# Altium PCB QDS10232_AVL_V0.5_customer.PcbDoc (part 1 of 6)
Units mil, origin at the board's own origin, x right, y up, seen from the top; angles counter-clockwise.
Board outline 3500 x 3799 mil, 6 copper layers (Top Layer, GND, INT1, PWR1, PWR2, Bottom Layer), stack 78.834 mil thick; 254 components, 204 nets, 7039 pads, 595 vias.
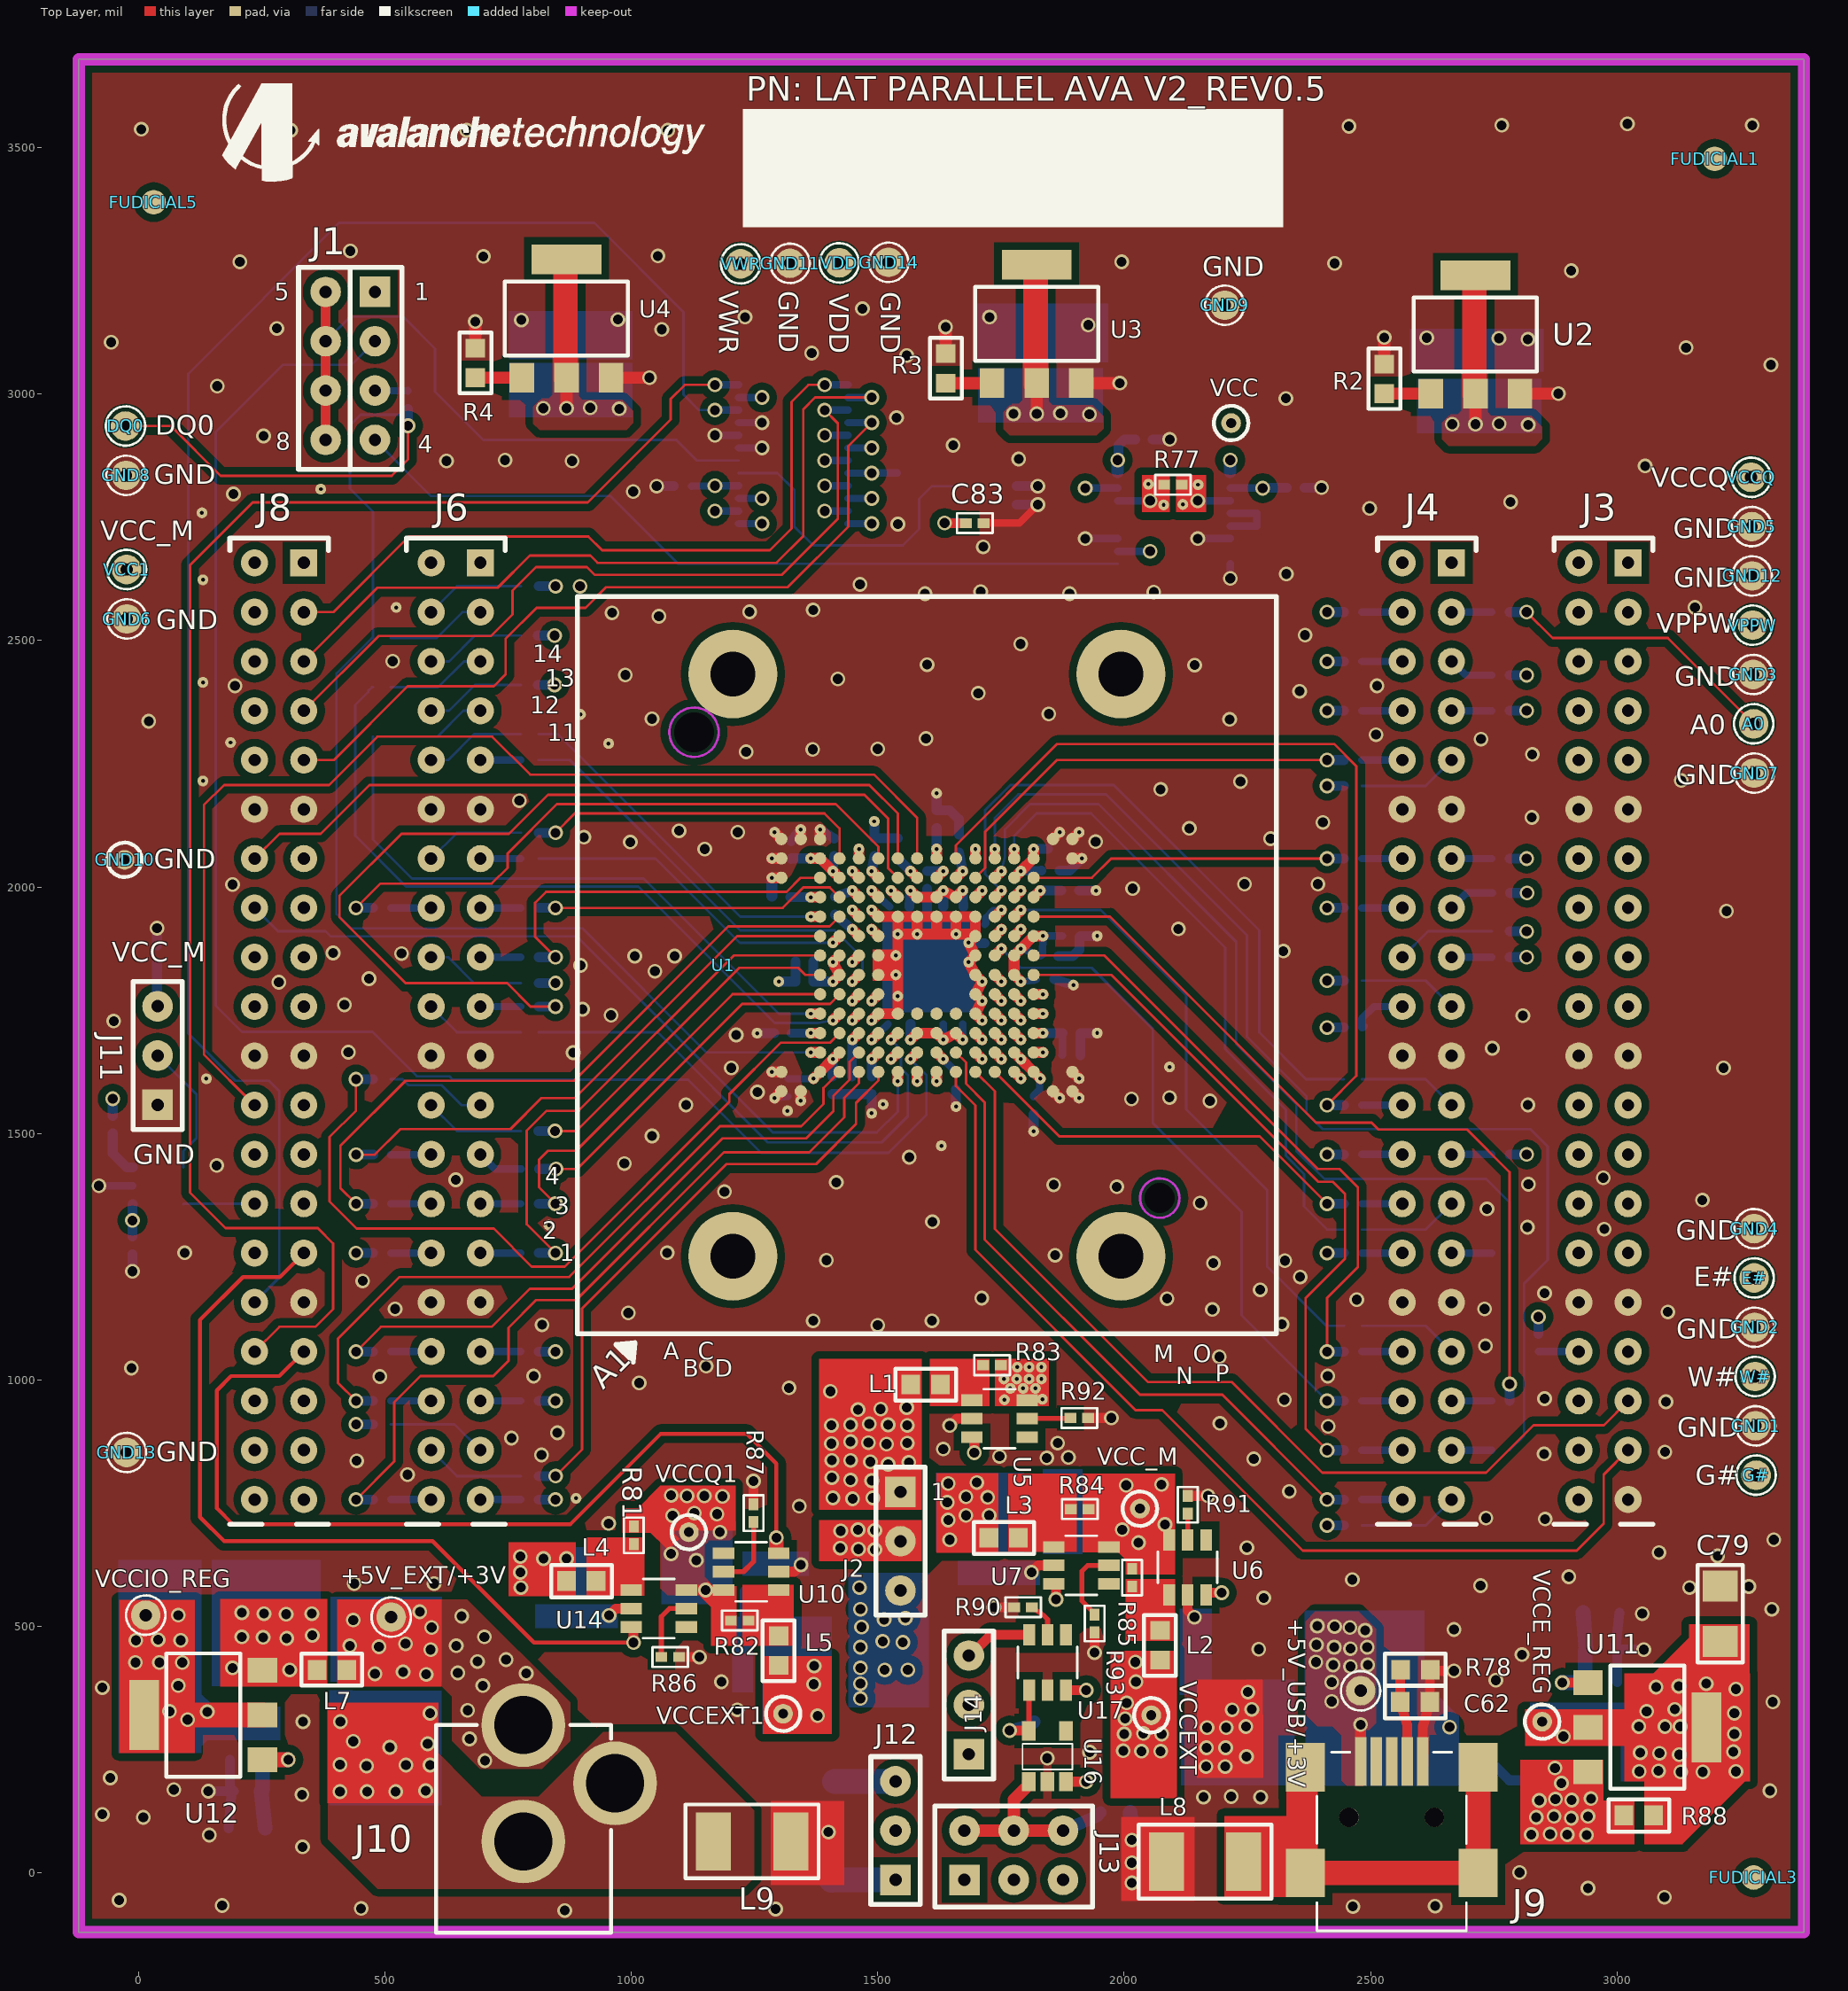
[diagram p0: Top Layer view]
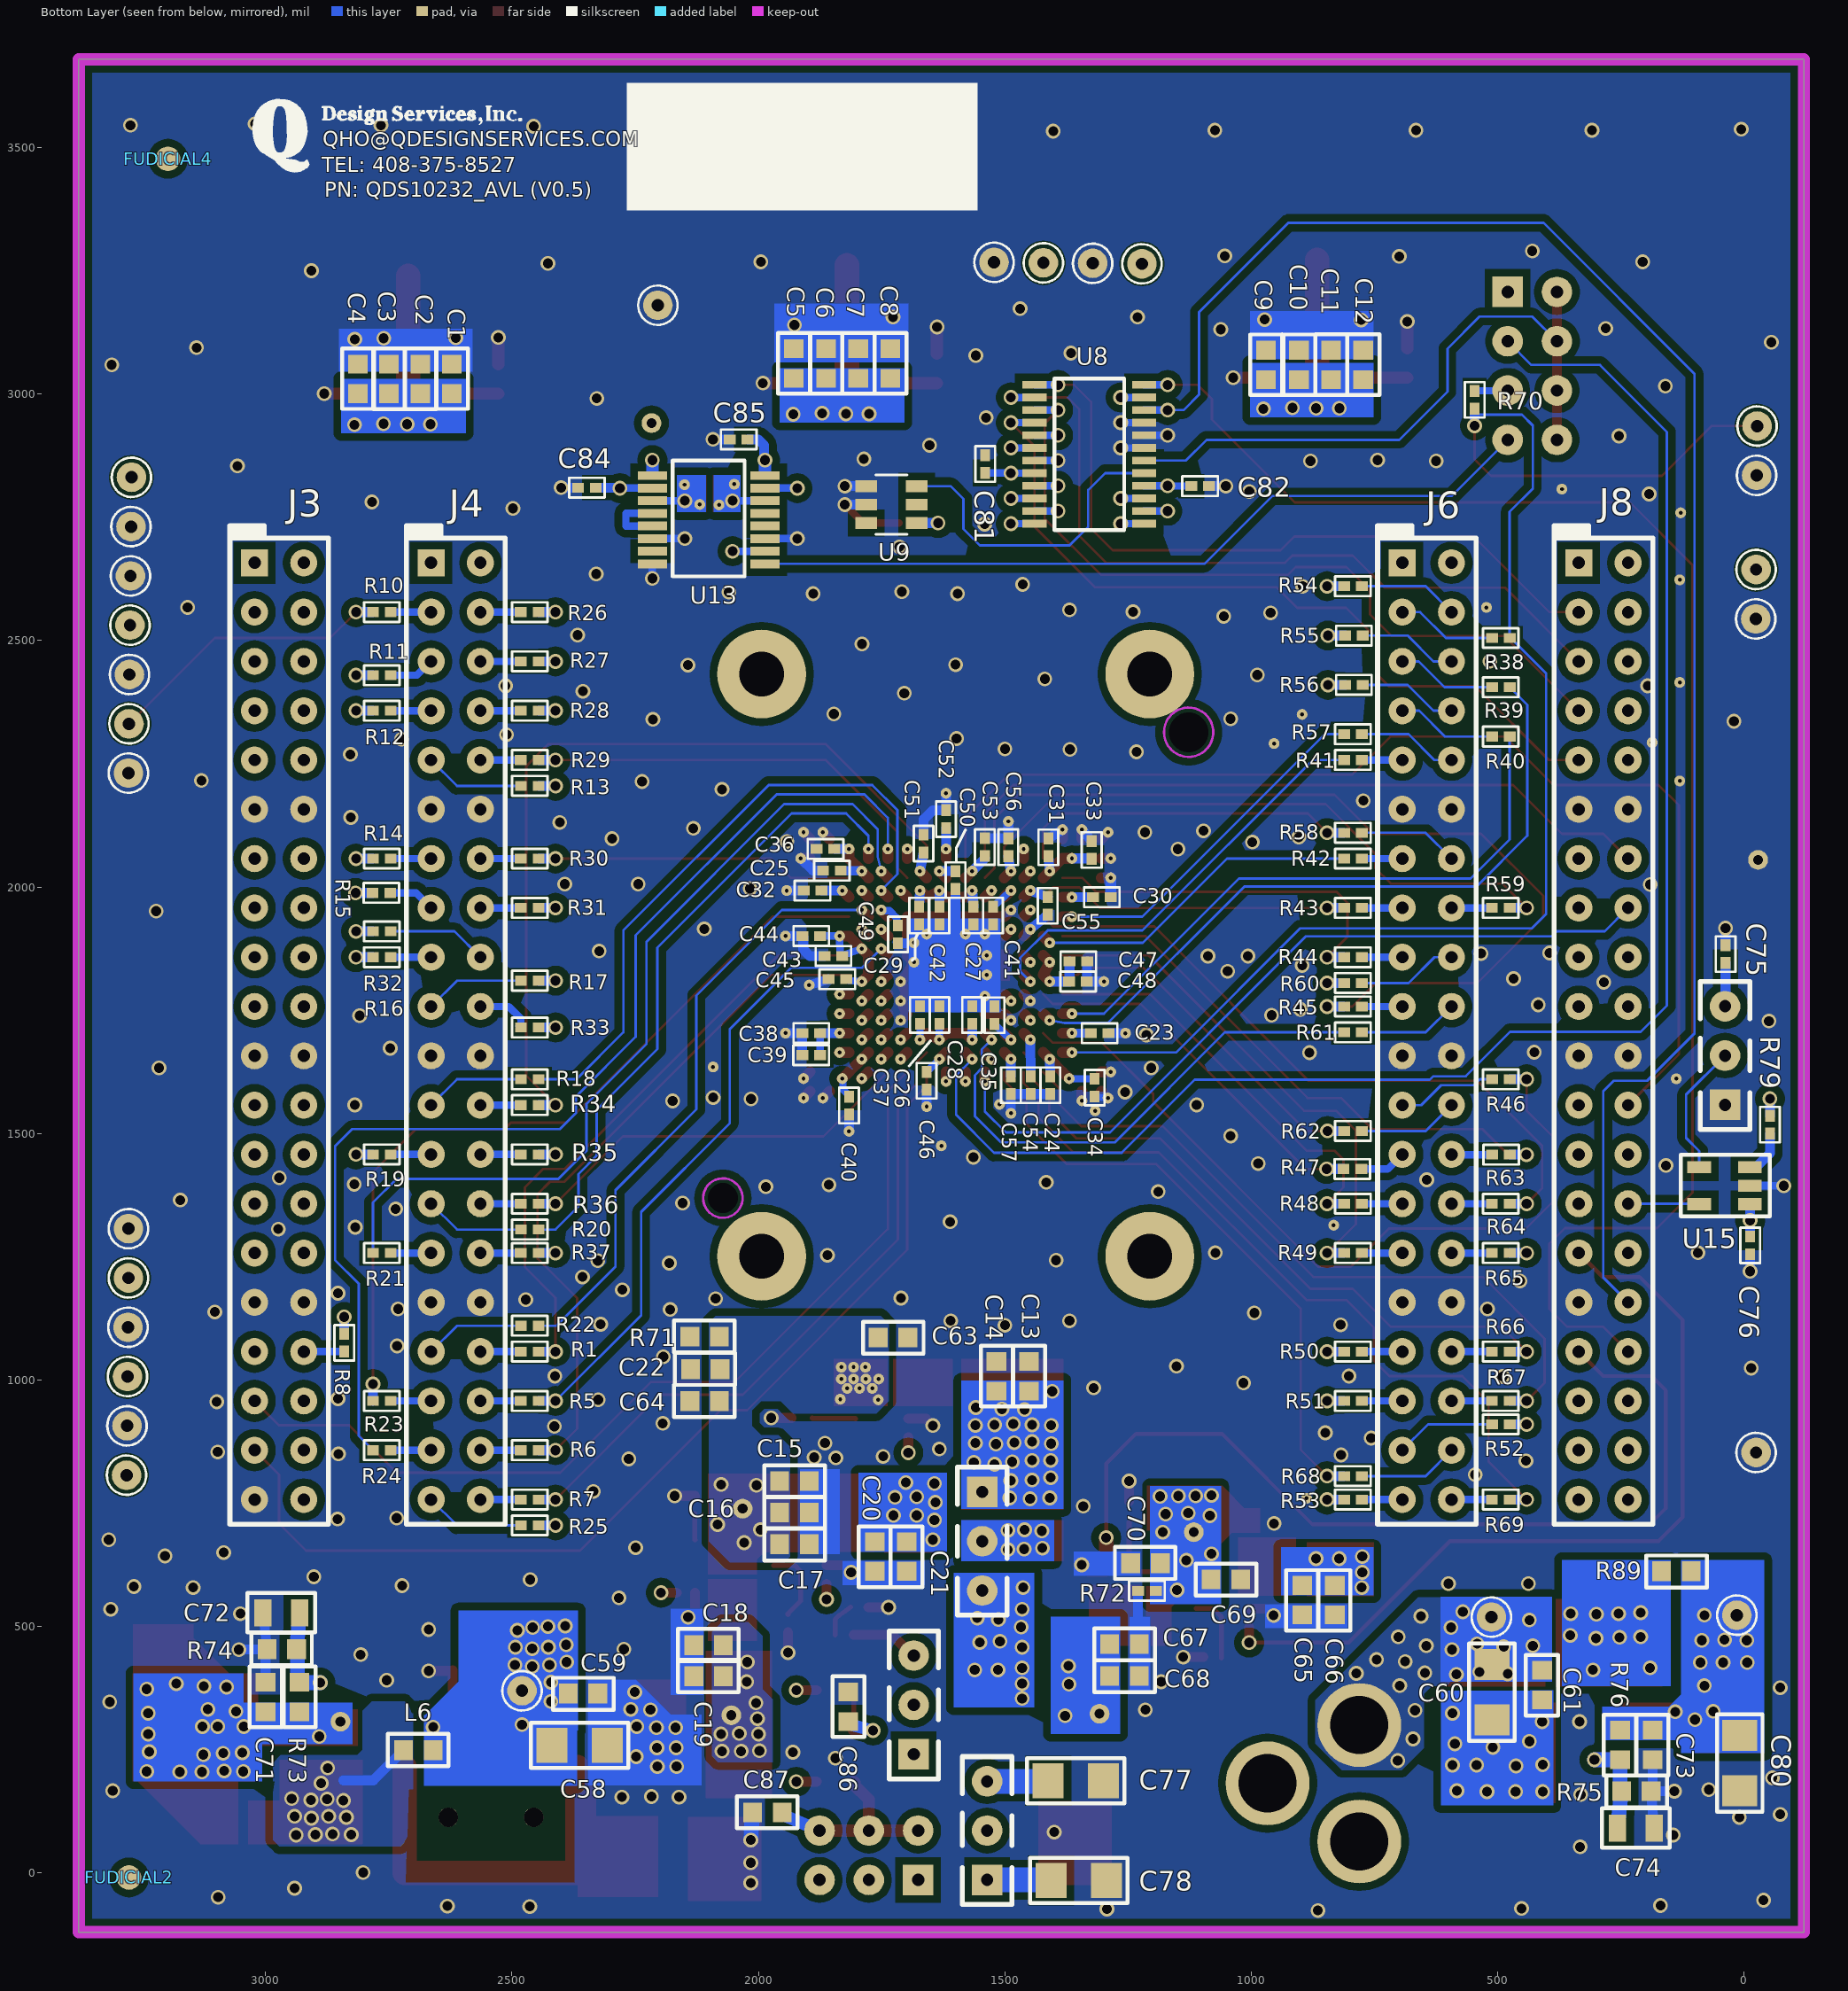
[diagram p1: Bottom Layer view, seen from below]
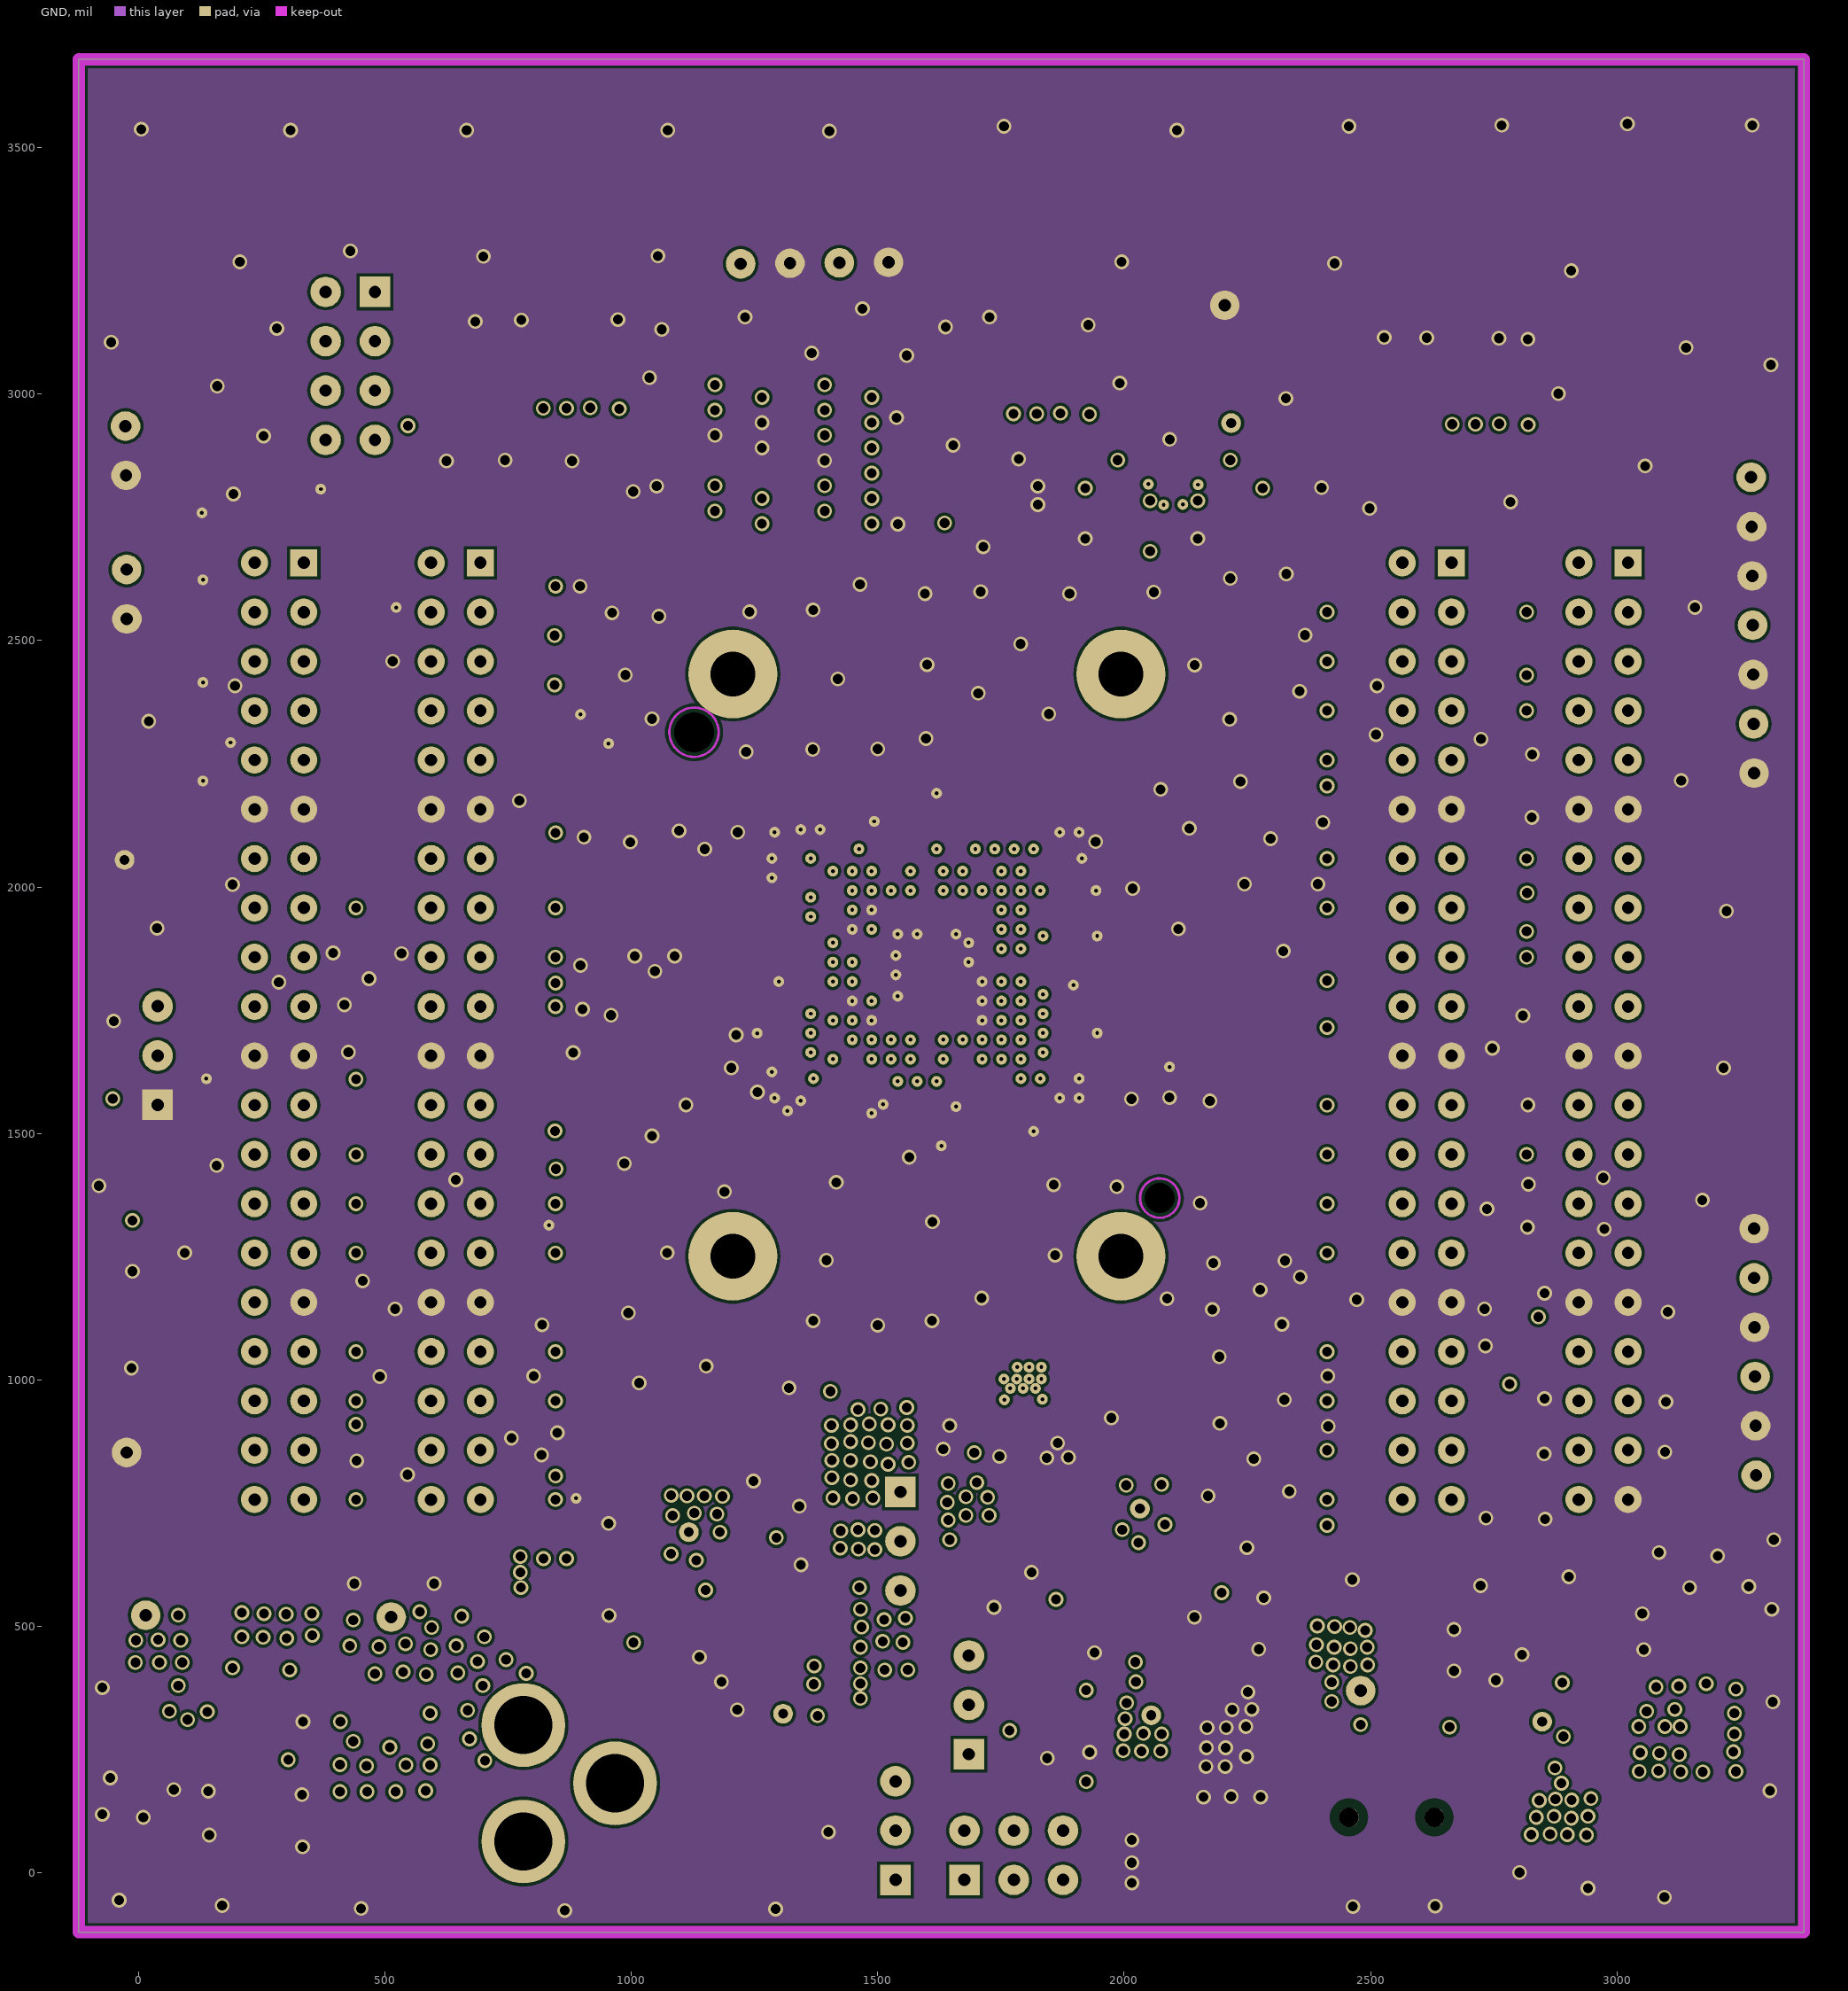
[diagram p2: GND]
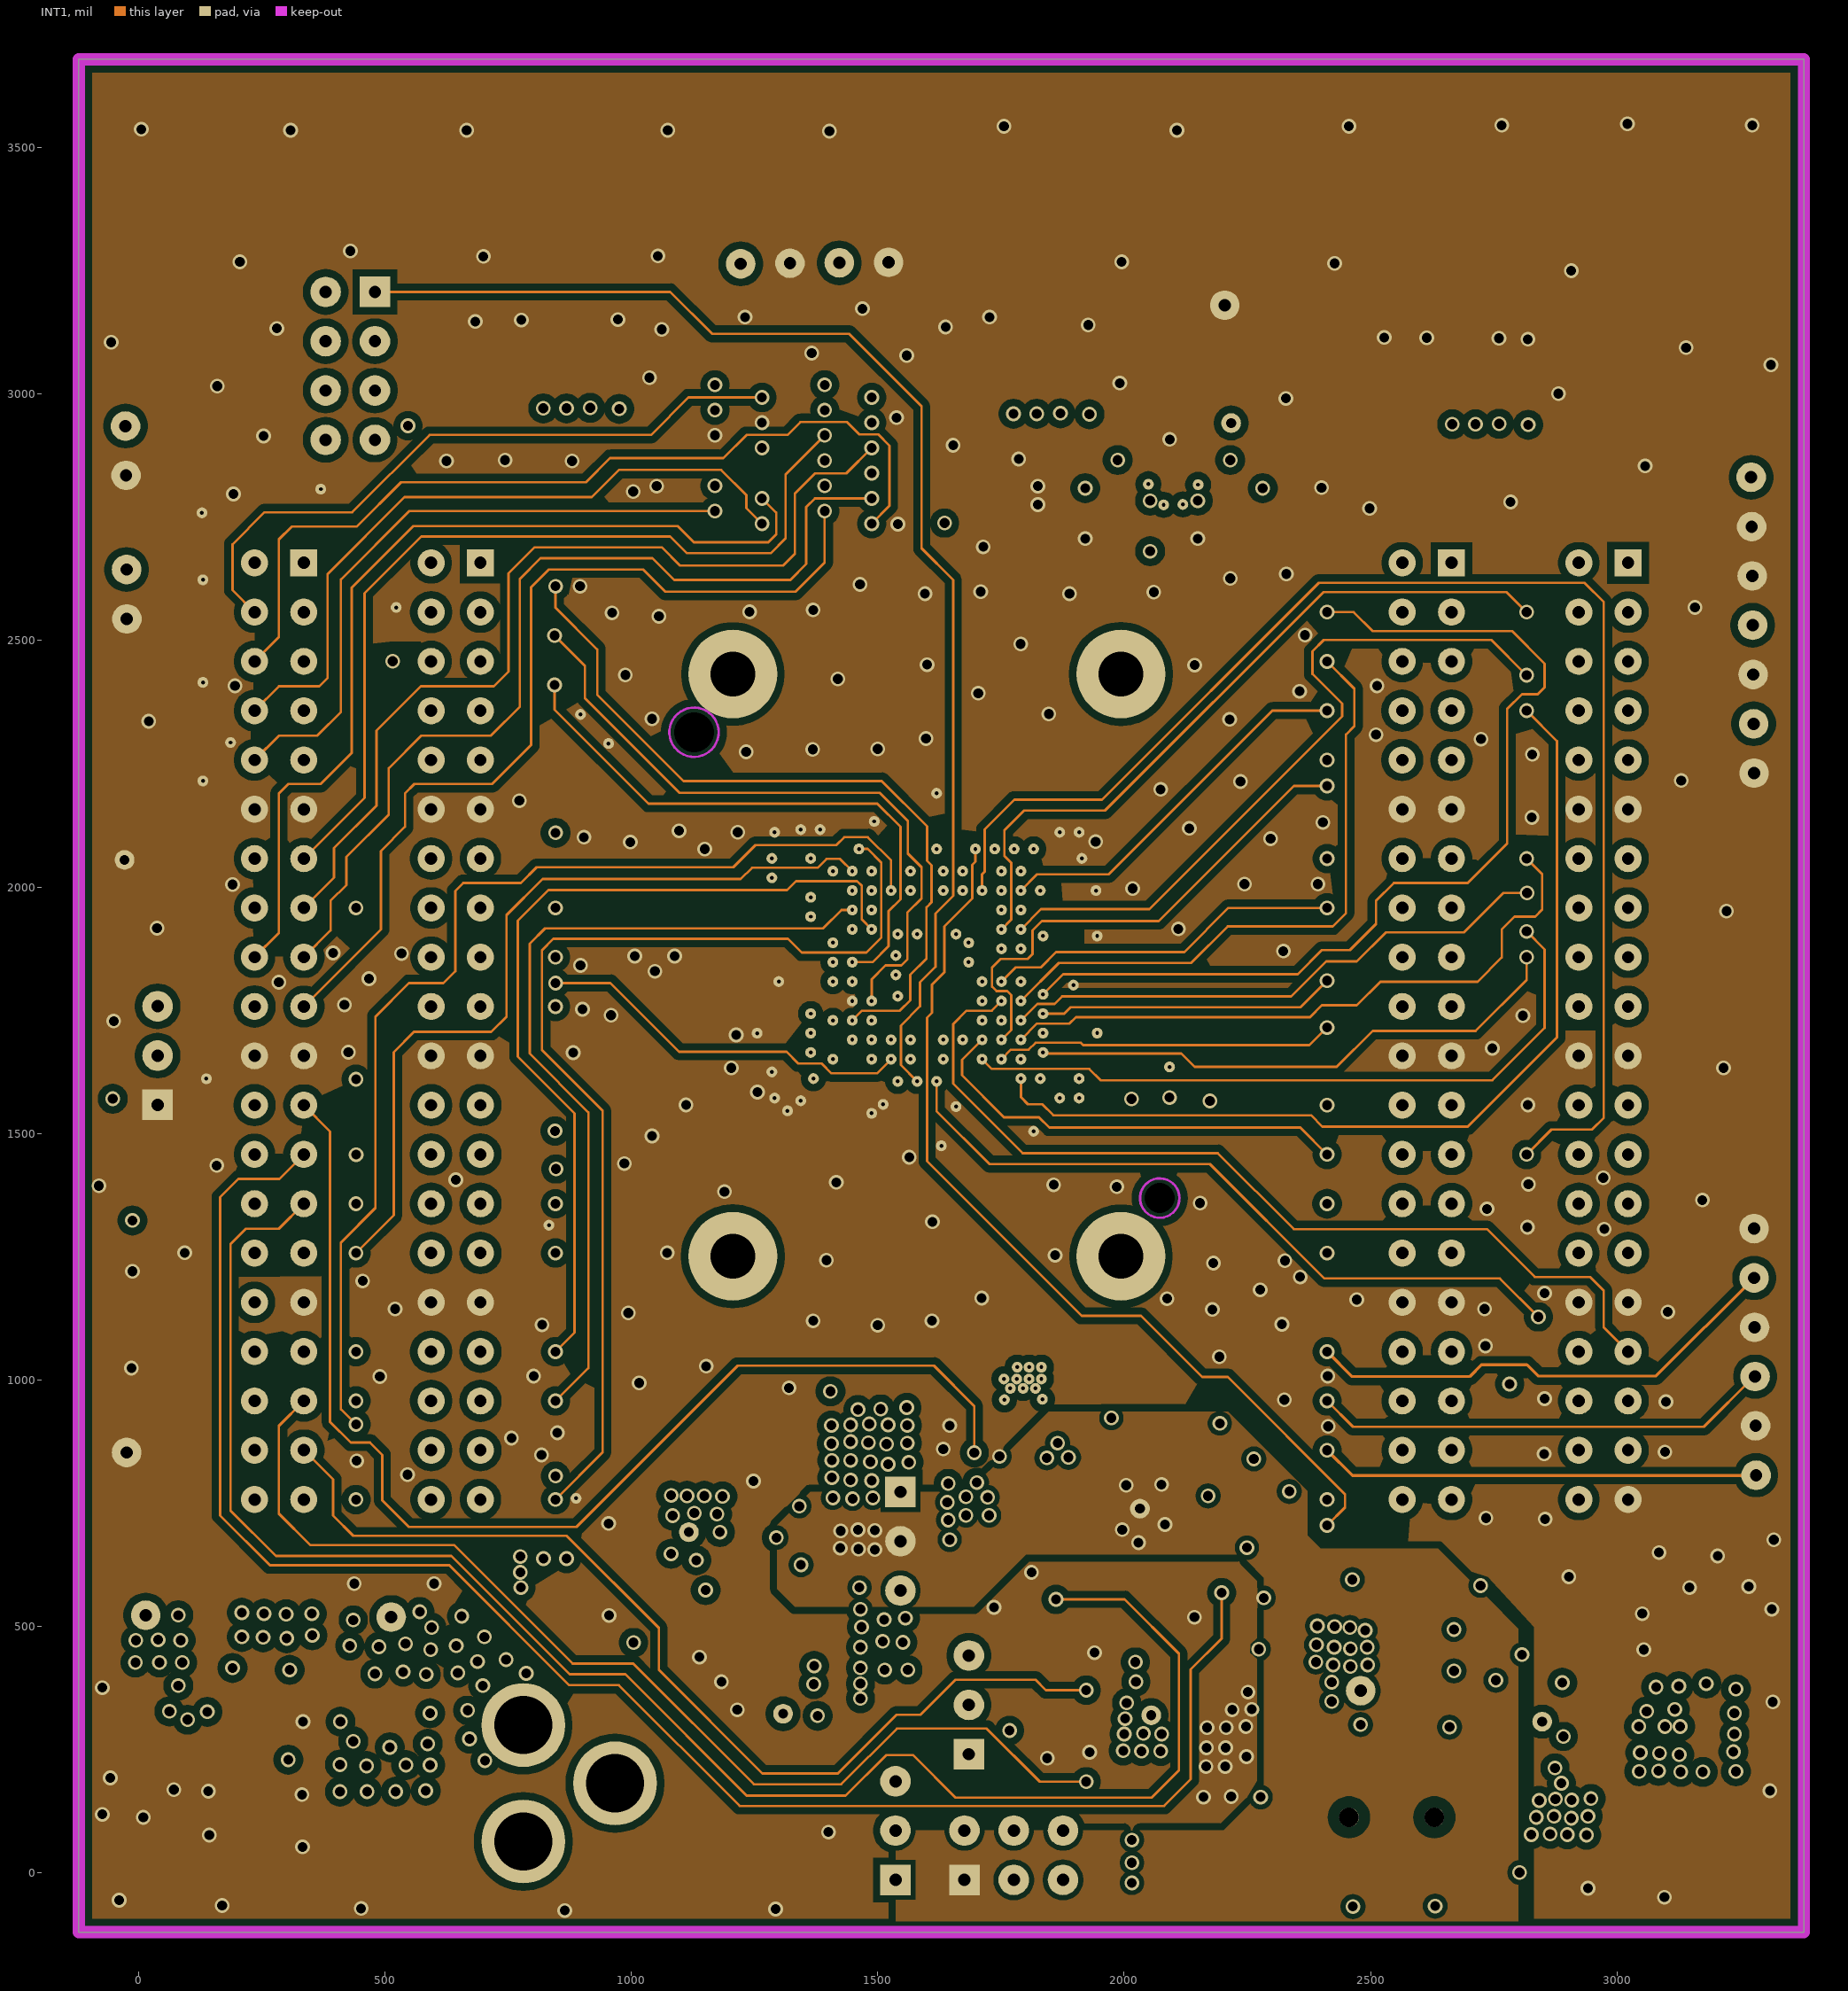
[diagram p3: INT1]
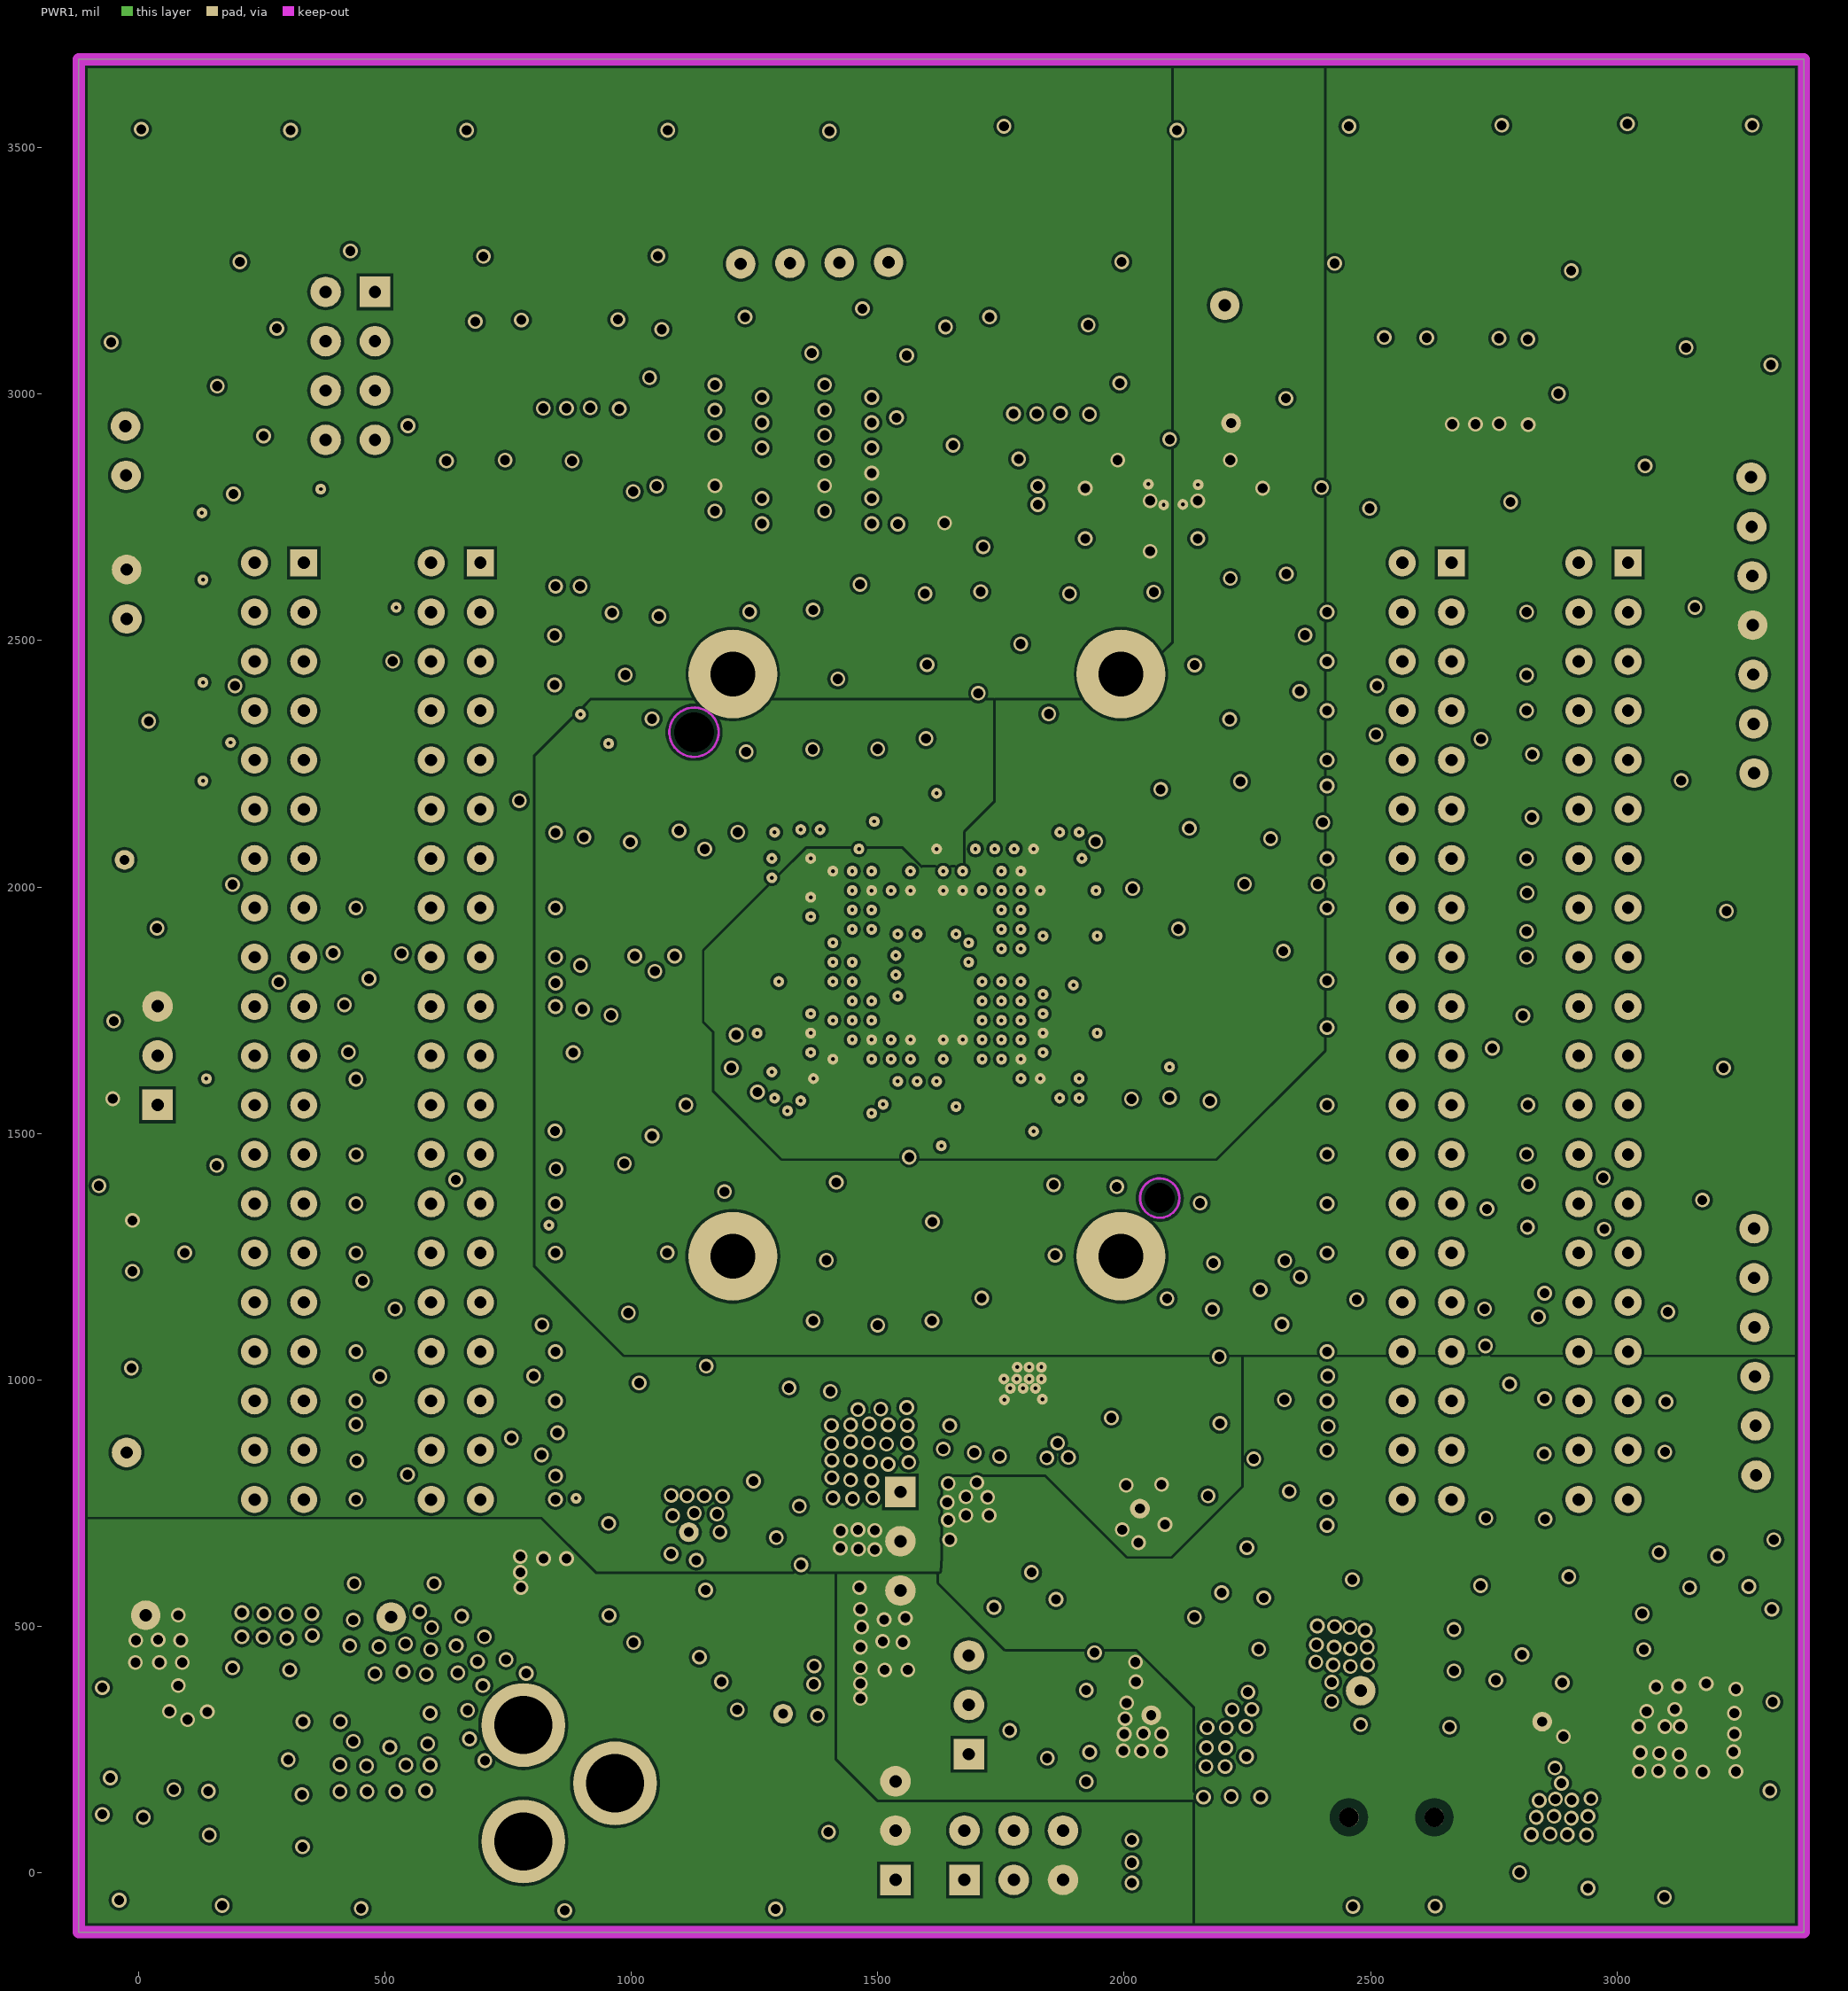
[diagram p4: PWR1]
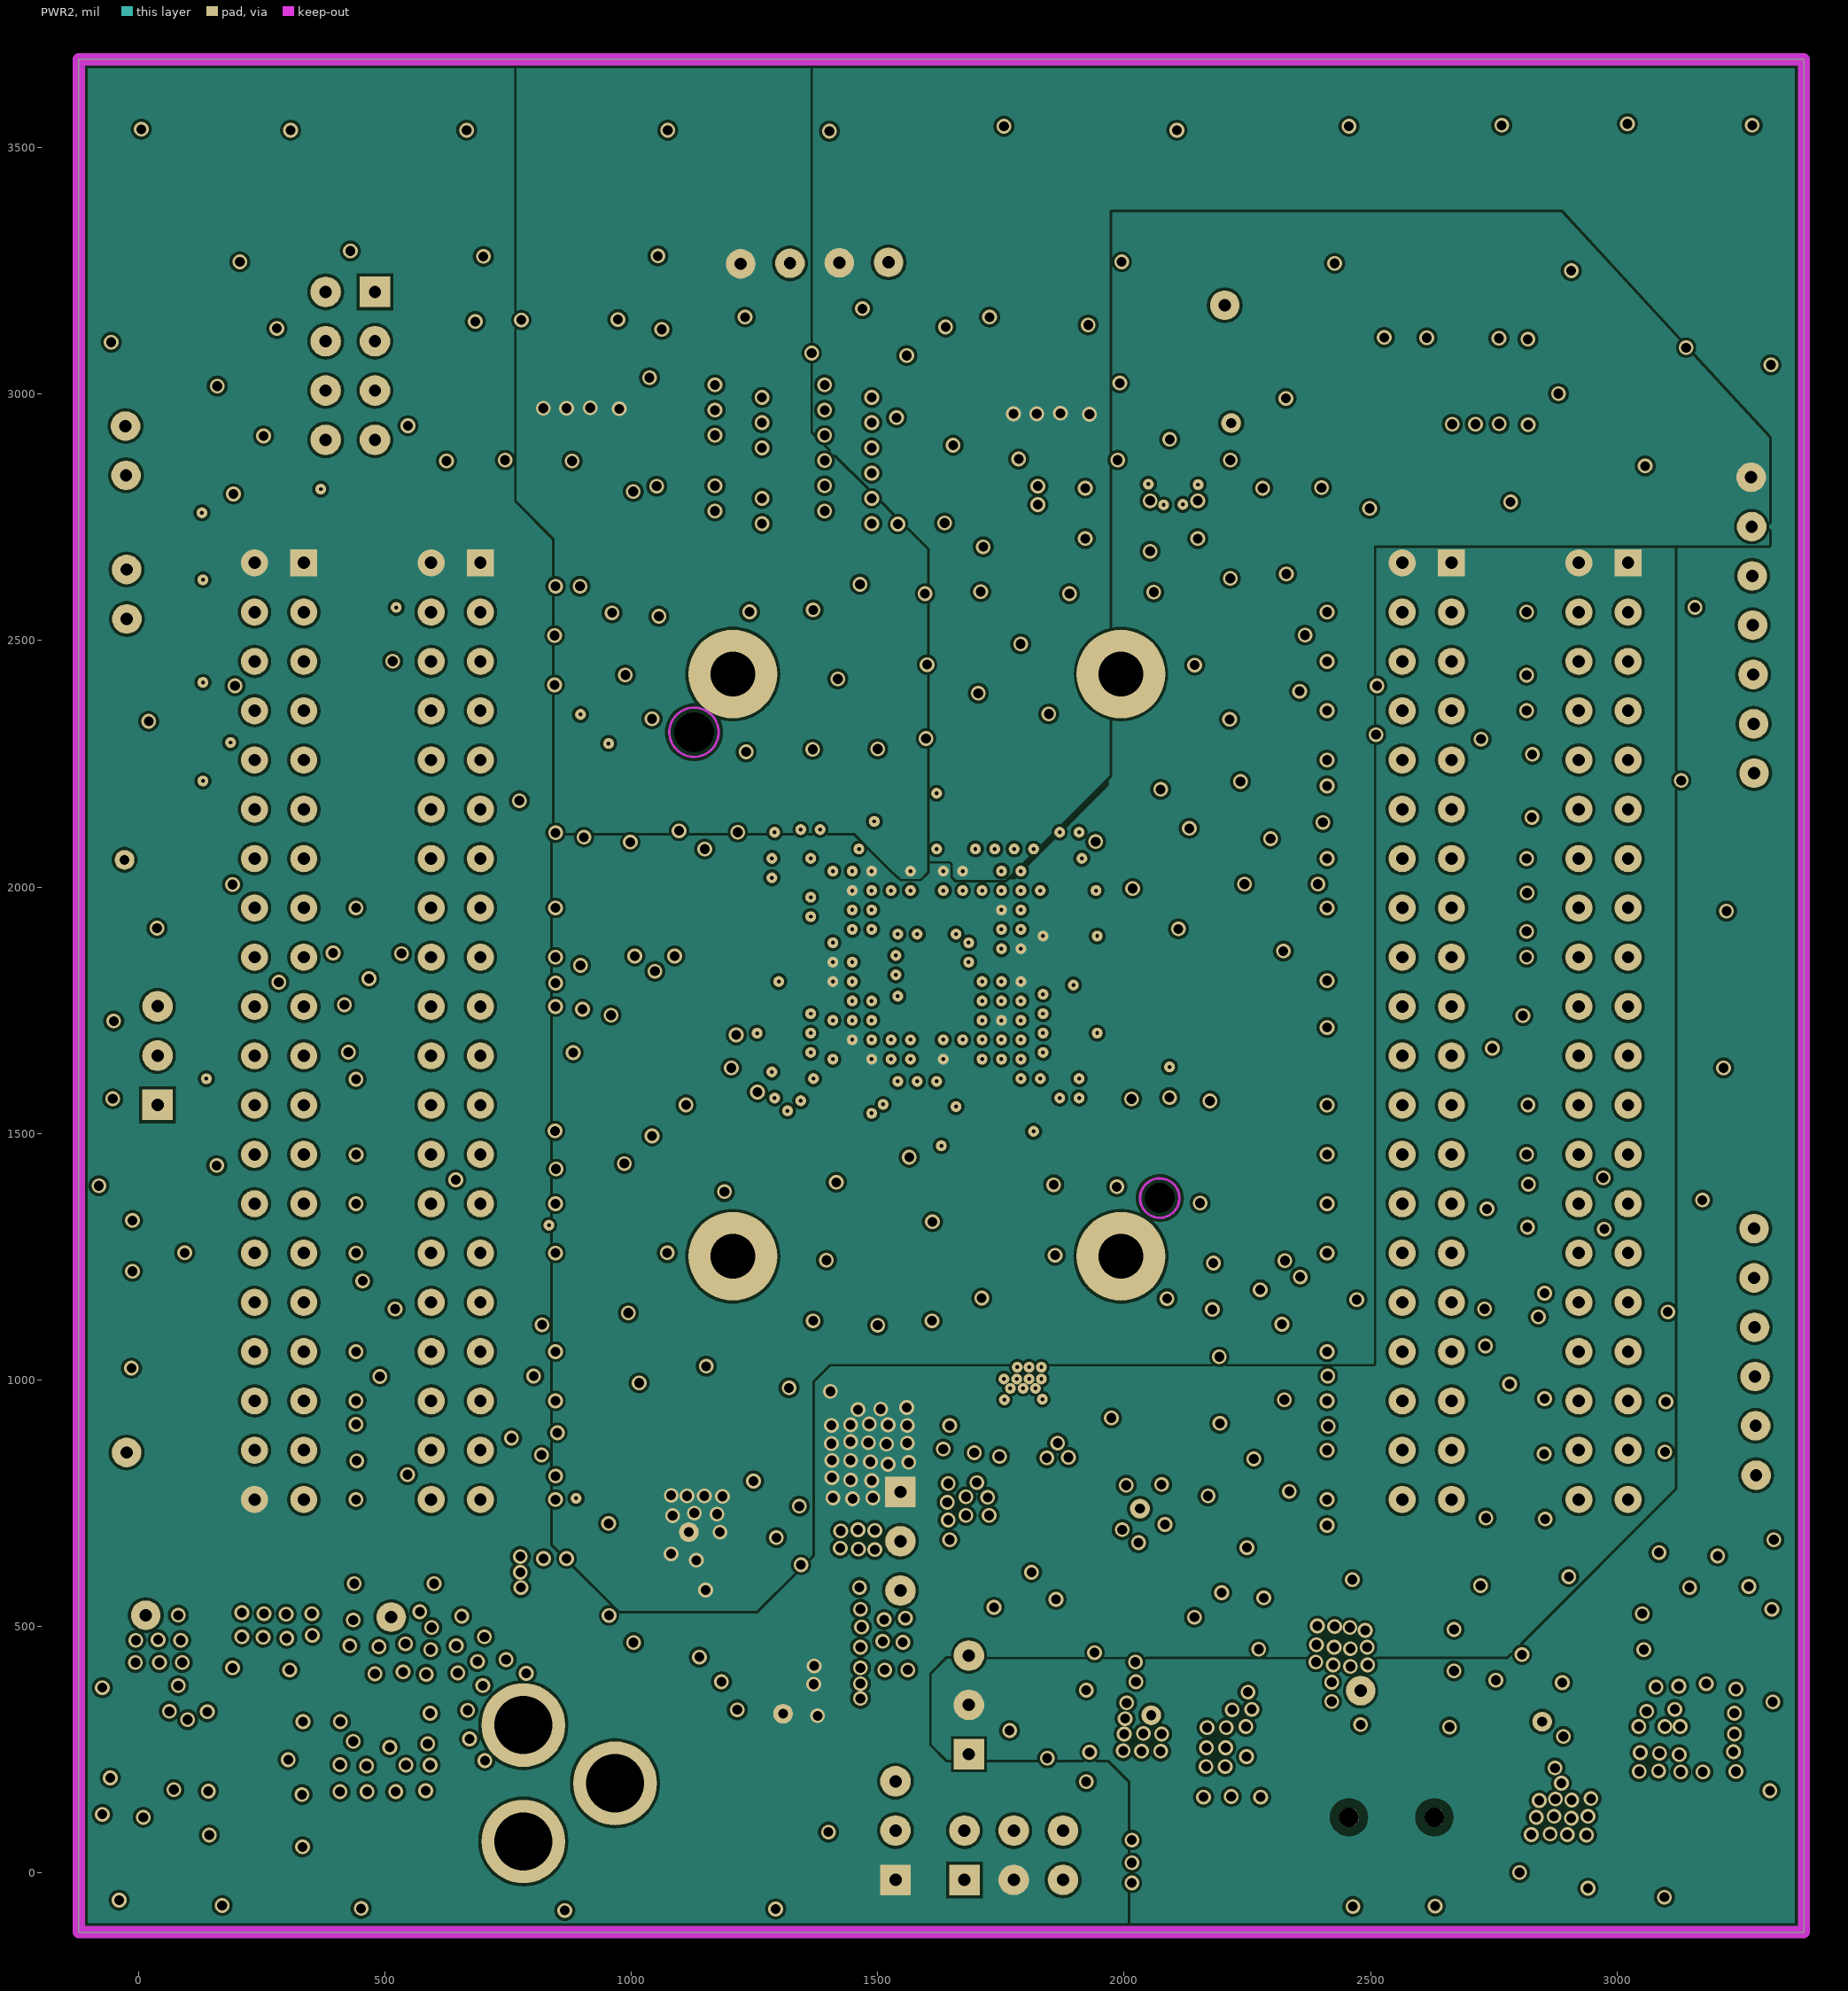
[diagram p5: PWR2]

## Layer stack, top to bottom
Top Solder: solder mask 1, Solder Resist, Dk 3.5
Top Layer: signal copper 6
Dielectric1: core 15, FR-4, Dk 4.2
GND: signal copper 2
Dielectric 8: prepreg 5, Dk 4.2
INT1: signal copper 1.417
Dielectric 10: core 10, Dk 4.2
Dielectric 12: prepreg 5, Dk 4.2
PWR1: signal copper 2
Dielectric 11: prepreg 5, Dk 4.2
PWR2: signal copper 1.417
Dielectric 7: core 10, Dk 4.2
Dielectric 6: core 10, Dk 4.2
Bottom Layer: signal copper 6
Bottom Solder: solder mask 1, Solder Resist, Dk 3.5

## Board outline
-121,-120 -121,3679 3379,3679 3379,-120

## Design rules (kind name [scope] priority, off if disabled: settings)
Clearance Clearance_1 [All] p1 off: gap=10 ignorepadtopadclearanceinfootprint=FALSE
Clearance [All] p2: gap=6 ignorepadtopadclearanceinfootprint=FALSE
ComponentClearance [All] p1 off: gap=10 collisioncheckmode=3 verticalgap=10 showdistances=FALSE
FabricationTestPointUsage TestPointUsage [All] p1: valid=0 allowmultiple=FALSE
FabricationTestpoint Testpoint [(IsPad And (OnTopLayer Or OnBottomLayer))] p1: side=3 testpointundercomponent=TRUE minsize=40 maxsize=100 preferedsize=60 minholesize=0 maxholesize=40 preferedholesize=32 testpointgrid=1 allowsidetop=TRUE allowsidebottom=TRUE usegrid=TRUE gridtolerance=0.01
Height [All] p1 off: minheight=0 maxheight=1000 prefheight=500
HoleSize [All] p1 off: absolutevalues=TRUE maxlimit=100 minlimit=1 maxpercent=80.000 minpercent=20.000
PlaneConnect [All] p1: planeconnectstyle=Relief reliefexpansion=25 reliefentries=4 reliefconductorwidth=10 reliefairgap=12
PolygonConnect THERMAL1 [InComponentClass('THERMAL1')] p1: connectstyle=Relief reliefconductorwidth=15 reliefentries=4 polygonreliefangle="90 Angle" airgapwidth=10
PolygonConnect [All] p2: connectstyle=Direct reliefconductorwidth=15 reliefentries=4 polygonreliefangle="45 Angle" airgapwidth=15
RoutingVias [All] p1: holewidth=20 width=40 viastyle="Through Hole" minholewidth=20 minwidth=40 maxholewidth=20 maxwidth=40
ShortCircuit [InNet('NetA401_1') vs InNet('GND')] p1: allowed=FALSE
SolderMaskExpansion [All] p1: expansion=2
Width Width_1 [All] p1: maxlimit=50 minlimit=4 preferedwidth=5
23 further rules are at their usual default settings.

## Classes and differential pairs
component class PAGE03_USB_REG: +5V_EXT/+3V +5V_USB/+3V C58 C59 C60 C61 C62 C65 C66 C67 C68 C69 C70 C71 C72 C73 C74 C78 C79 C80 C84 C85 C86 C87 J9 J10 J12 J13 J14 L4 L5 L6 L7 L8 L9 R72 R73 R74 R75 R76 R77 R78 R81 R82 R86 R87 R88 R89 R90 U10 U11 U12 U13 U14 U16 U17 VCCE_REG VCCEXT1 VCCIO_REG VCCQ1
component class PAGE02_CIRCUIT: A0 C1 C2 C3 C4 C5 C6 C7 C8 C9 C10 C11 C12 C13 C14 C15 C16 C17 C18 C19 C20 C21 C22 C63 C64 C75 C76 C77 C81 C82 C83 DQ0 E# G# GND1 GND2 GND3 GND4 GND5 GND6 GND7 GND8 GND9 GND10 GND11 GND12 GND13 GND14 J1 J2 J11 L1 L2 L3 R2 R3 R4 R70 R71 R79 R83 R84 R85 R91 R92 R93 U2 U3 U4 U5 U6 U7 U8 U9 U15 VCC1 VCC_M VCCEXT VCCQ VDD VPPW VWR W#
component class PAGE01_BGA: C23 C24 C25 C26 C27 C28 C29 C30 C31 C32 C33 C34 C35 C36 C37 C38 C39 C40 C41 C42 C43 C44 C45 C46 C47 C48 C49 C50 C51 C52 C53 C54 C55 C56 C57 U1 VCC
component class PAGE04_CON_J3-J4-J6-J8: FUDICIAL1 FUDICIAL2 FUDICIAL3 FUDICIAL4 FUDICIAL5 J3 J4 J6 J8 R1 R5 R6 R7 R8 R10 R11 R12 R13 R14 R15 R16 R17 R18 R19 R20 R21 R22 R23 R24 R25 R26 R27 R28 R29 R30 R31 R32 R33 R34 R35 R36 R37 R38 R39 R40 R41 R42 R43 R44 R45 R46 R47 R48 R49 R50 R51 R52 R53 R54 R55 R56 R57 R58 R59 R60 R61 R62 R63 R64 R65 R66 R67 R68 R69

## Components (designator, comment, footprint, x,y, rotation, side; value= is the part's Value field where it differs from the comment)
+5V_EXT/+3V "TESTPOINT" "TEST POINT" 513,519 r90 top value="COPPER FEATURE"
+5V_USB/+3V "TESTPOINT" "TEST POINT" 2479.62,369.62 r90 top value="COPPER FEATURE"
A0 "" "TEST POINT" 3277,2331 r90 top value="COPPER FEATURE"
C1 "DNI" N_0603 2621.97,3030.71 r90 bottom
C2 "DNI" N_0603 2685.7,3030.64 r90 bottom
C3 "DNI" N_0603 2749.7,3030.64 r90 bottom
C4 "DNI" N_0603 2812.7,3030.71 r90 bottom
C5 "DNI" N_0603 1928.52,3062 r90 bottom
C6 "DNI" N_0603 1862.52,3062 r90 bottom
C7 "DNI" N_0603 1797.52,3062 r90 bottom
C8 "DNI" N_0603 1732.52,3062 r90 bottom
C9 "DNI" N_0603 970.23,3058.71 r90 bottom
C10 "DNI" N_0603 903.23,3058.71 r90 bottom
C11 "DNI" N_0603 838.23,3058.71 r90 bottom
C12 "DNI" N_0603 773.23,3058.71 r90 bottom
C13 "0.01uF" N_0603 1451,1007.5 r90 bottom
C14 "0.1uF" N_0603 1517,1007.5 r90 bottom
C15 "0.01uF" N_0603 1927,795 r180 bottom
C16 "0.1uF" N_0603 1927,731 r180 bottom
C17 "4.7uF" N_0603 1927,667 r180 bottom
C18 "DNI" N_0603 2101,462 r0 bottom
C19 "DNI" N_0603 2101,399 r0 bottom
C20 "DNI" N_0603 1764,642 r270 bottom
C21 "DNI" N_0603 1699,642 r270 bottom
C22 "DNI" N_0603 2108,1022 r0 bottom
C23 "0.1uF" N_0402 1307.7,1703.45 r180 bottom
C24 "0.1uF" N_0402 1407.71,1598 r270 bottom
C25 "0.1uF" N_0402 1851,2033 r0 bottom
C26 "0.1uF" N_0402 1632.95,1740.45 r90 bottom
C27 "0.1uF" N_0402 1564,1942 r270 bottom
C28 "0.1uF" N_0402 1566.45,1740.45 r90 bottom
C29 "0.1uF" N_0402 1674,1942 r270 bottom
C30 "0.1uF" N_0402 1303.24,1979.24 r180 bottom
C31 "0.1uF" N_0402 1411.7,2080.45 r90 bottom
C32 "0.1uF" N_0402 1890.32,1992.81 r0 bottom
C33 "0.1uF" N_0402 1324,2075 r90 bottom
C34 "0.1uF" N_0402 1318,1593 r270 bottom
C35 "0.1uF" N_0402 1521,1740 r90 bottom
C36 "0.1uF" N_0402 1863.83,2077.17 r0 bottom
C37 "0.1uF" N_0402 1672.32,1740.45 r90 bottom
C38 "0.1uF" N_0402 1892.8,1703.65 r0 bottom
C39 "0.1uF" N_0402 1893,1659 r0 bottom
C40 "0.1uF" N_0402 1816.24,1556.76 r270 bottom
C41 "0.1uF" N_0402 1524,1942 r270 bottom
C42 "0.1uF" N_0402 1633,1942 r270 bottom
C43 "0.1uF" N_0402 1848,1860 r0 bottom
C44 "0.1uF" N_0402 1892.8,1900.5 r0 bottom
C45 "0.1uF" N_0402 1840,1813 r0 bottom
C46 "0.1uF" N_0402 1658.76,1606.91 r270 bottom
C47 "0.1uF" N_0402 1351,1849 r180 bottom
C48 "0.1uF" N_0402 1351.59,1808.2 r180 bottom
C49 "0.1uF" N_0402 1717,1904 r270 bottom
C50 "0.1uF" N_0402 1600,2014 r270 bottom
C51 "DNI" N_0402 1665,2088 r90 bottom
C52 "DNI" N_0402 1619.39,2137.69 r90 bottom
C53 "DNI" N_0402 1540.65,2080.98 r90 bottom
C54 "0.1uF" N_0402 1447.71,1598 r270 bottom
C55 "0.1uF" N_0402 1413,1961.99 r270 bottom
C56 "0.1uF" N_0402 1492.98,2080.65 r90 bottom
C57 "0.1uF" N_0402 1487.71,1598 r270 bottom
C58 "DNI" N_1206 2363,259 r180 bottom
C59 "DNI" N_0603 2356,364 r180 bottom
C60 "DNI" N_1206 511.96,367.1 r270 bottom
C61 "DNI" N_0603 410,381 r270 bottom
C62 "DNI" N_0603 2590,347 r0 top
C63 "DNI" N_0603 1727,1086 r180 bottom
C64 "DNI" N_0603 2109,957 r0 bottom
C65 "0.01uF" N_0603 896.82,553.4 r270 bottom
C66 "0.1uF" N_0603 830.82,553.4 r270 bottom
C67 "DNI" N_0603 1257.38,464.4 r180 bottom
C68 "DNI" N_0603 1257.38,399.4 r180 bottom
C69 "0.01uF" N_0603 1051.82,595.4 r180 bottom
C70 "DNI" N_0603 1214.82,628.4 r0 bottom
C71 "DNI" N_0603 3000,357 r90 bottom
C72 "DNI" N_0805 2968,528 r0 bottom
C73 "DNI" N_0603 186,260 r270 bottom
C74 "DNI" N_0805 220,91 r180 bottom
C75 "DNI" N_0402 38,1864 r270 bottom
C76 "DNI" N_0402 -12,1273 r90 bottom
C77 "DNI" N_1206 1356,187 r180 bottom
C78 "DNI" N_1206 1350,-15 r180 bottom
C79 "DNI" N_1206 3209,526 r90 top
C80 "DNI" N_1206 9,223 r270 bottom
C81 "DNI" N_0402 1540,2858 r90 bottom
C82 "DNI" N_0402 1104,2813 r180 bottom
C83 "DNI" N_0402 1697,2738 r0 top
C84 "DNI" N_0402 2348,2810 r0 bottom
C85 "DNI" N_0402 2040,2908 r0 bottom
C86 "1uF" N_0603 1818,337 r90 bottom
C87 "1uF" N_0603 1982,123 r0 bottom
DQ0 "" "TEST POINT" -26,2935 r90 top value="COPPER FEATURE"
E# "" "TEST POINT" 3278,1207 r90 top value="COPPER FEATURE"
FUDICIAL1 "FUDICIAL" FUDICIAL 3198,3477 r90 top
FUDICIAL2 "FUDICIAL" FUDICIAL 3277,-9 r180 bottom
FUDICIAL3 "FUDICIAL" FUDICIAL 3277,-9 r90 top
FUDICIAL4 "FUDICIAL" FUDICIAL 3198,3477 r90 bottom
FUDICIAL5 "FUDICIAL" FUDICIAL 31,3389 r90 top
G# "" "TEST POINT" 3282,807 r90 top value="COPPER FEATURE"
GND1 "GND" "TEST POINT" 3281,907 r180 top value="COPPER FEATURE"
GND2 "GND" "TEST POINT" 3279,1107 r180 top value="COPPER FEATURE"
GND3 "GND" "TEST POINT" 3276,2431 r180 top value="COPPER FEATURE"
GND4 "GND" "TEST POINT" 3278,1307 r180 top value="COPPER FEATURE"
GND5 "GND" "TEST POINT" 3273,2731 r90 top value="COPPER FEATURE"
GND6 "GND" "TEST POINT" -23.3,2543.7 r90 top value="COPPER FEATURE"
GND7 "GND" "TEST POINT" 3278,2231 r90 top value="COPPER FEATURE"
GND8 "GND" "TEST POINT" -25,2835 r180 top value="COPPER FEATURE"
GND9 "GND" "TEST POINT" 2204,3180 r180 top value="COPPER FEATURE"
GND10 "GND" "TEST POINT 40X20_010819" -28,2055.02 r180 top value="COPPER FEATURE"
GND11 "GND" "TEST POINT" 1322,3265 r180 top value="COPPER FEATURE"
GND12 "GND" "TEST POINT" 3274,2631 r180 top value="COPPER FEATURE"
GND13 "GND" "TEST POINT" -24,853 r180 top value="COPPER FEATURE"
GND14 "GND" "TEST POINT" 1522,3267 r270 top value="COPPER FEATURE"
J1 "10PIN-JUMPER" 1X5_HDR 480,3057 r270 top locked
J2 "3PIN-JUMPER" JUMPER_3PIN 1546,673 r270 top
J3 "J3_2X10" 2X10-HEADER 2972.31,1707.56 r270 bottom locked
J4 "J4_2X10" 2X10-HEADER 2614.04,1707.56 r270 bottom locked
J6 "J6_2X10" 2X10-HEADER 643.96,1707.56 r270 bottom locked
J8 "J8_2X10" 2X10-HEADER 285.69,1707.56 r270 bottom locked
J9 "MUSB-05-S-B-SM-A" MUSB-05-S-B-SM-A 2542.61,226.39 r180 top locked
J10 "POWER_JACK" POWER_JACK_PTH 781,-240 r0 top locked
J11 "3PIN-JUMPER" JUMPER_3PIN 39,1658 r90 top
J12 "3PIN-JUMPER" JUMPER_3PIN 1536,86 r90 top
J13 "4PIN-JUMPER" 1X4_HDR 1826,-14 r0 top
J14 "3PIN-JUMPER" JUMPER_3PIN 1685,341 r90 top
L1 "BLM18SG121TN1D" N_0603 1597,991 r0 top value="120 OHM"
L2 "DNI" N_0603 2073,462 r270 top
L3 "DNI" N_0603 1755.59,680 r0 top
L4 "BLM18SG121TN1D" N_0603 898.41,592.4 r0 top value="120 OHM"
L5 "DNI" N_0603 1299,451 r270 top
L6 "DNI" N_0603 2690,249 r0 bottom
L7 "DNI, SHORT IT ACROSS" N_0603 393,411.94 r180 top value=DNI
L8 "DNI" FB_2743019447 2164,23 r0 top
L9 "2743019447" FB_2743019447 1245,64 r180 top
R1 "39 1%" N_0402 2464.04,1057.56 r180 bottom
R2 "DNI" N_0603 2527.7,3030.71 r90 top
R3 "DNI" N_0603 1637.7,3052 r90 top
R4 "DNI" N_0603 683.7,3063 r90 top
R5 "39 1%" N_0402 2464.04,957.56 r180 bottom
R6 "39 1%" N_0402 2464.04,857.56 r180 bottom
R7 "39 1%" N_0402 2464.04,757.56 r180 bottom
R8 "39 1%" N_0402 2840.31,1075.56 r90 bottom
R10 "39 1%" N_0402 2764.04,2557.56 r0 bottom
R11 "39 1%" N_0402 2763.96,2429.56 r0 bottom
R12 "39 1%" N_0402 2764.04,2357.56 r0 bottom
R13 "39 1%" N_0402 2464,2205.12 r180 bottom
R14 "39 1%" N_0402 2764.04,2057.56 r0 bottom
R15 "39 1%" N_0402 2765,1988 r0 bottom
R16 "39 1%" N_0402 2764.04,1857.56 r0 bottom
R17 "39 1%" N_0402 2464,1810 r180 bottom
R18 "39 1%" N_0402 2464,1610 r180 bottom
R19 "39 1%" N_0402 2764.04,1457.56 r0 bottom
R20 "39 1%" N_0402 2464,1305.12 r180 bottom
R21 "39 1%" N_0402 2764.04,1257.56 r0 bottom
R22 "39 1%" N_0402 2464,1110 r180 bottom
R23 "39 1%" N_0402 2764.04,957.56 r0 bottom
R24 "39 1%" N_0402 2764.04,857.56 r0 bottom
R25 "39 1%" N_0402 2464,705.12 r180 bottom
R26 "39 1%" N_0402 2464.04,2557.56 r180 bottom
R27 "39 1%" N_0402 2464.04,2457.56 r180 bottom
R28 "39 1%" N_0402 2464.04,2357.56 r180 bottom
R29 "39 1%" N_0402 2464.04,2257.56 r180 bottom
R30 "39 1%" N_0402 2464.04,2057.56 r180 bottom
R31 "39 1%" N_0402 2464.04,1957.56 r180 bottom
R32 "39 1%" N_0402 2764.08,1910 r0 bottom
R33 "39 1%" N_0402 2464,1715 r180 bottom
R34 "39 1%" N_0402 2464.04,1557.56 r180 bottom
R35 "39 1%" N_0402 2464.04,1457.56 r180 bottom
R36 "39 1%" N_0402 2464.04,1357.56 r180 bottom
R37 "39 1%" N_0402 2464.04,1257.56 r180 bottom
R38 "39 1%" N_0402 493.92,2505.12 r180 bottom
R39 "39 1%" N_0402 493.92,2405.12 r180 bottom
R40 "39 1%" N_0402 493.92,2305.12 r180 bottom
R41 "39 1%" N_0402 793.96,2257.56 r0 bottom
R42 "39 1%" N_0402 793.96,2057.56 r0 bottom
R43 "39 1%" N_0402 793.96,1957.56 r0 bottom
R44 "39 1%" N_0402 793.96,1857.56 r0 bottom
R45 "39 1%" N_0402 793.96,1757.56 r0 bottom
R46 "39 1%" N_0402 493.92,1610 r180 bottom
R47 "39 1%" N_0402 795,1428 r0 bottom
R48 "39 1%" N_0402 793.96,1357.56 r0 bottom
R49 "39 1%" N_0402 793.96,1257.56 r0 bottom
R50 "39 1%" N_0402 793.96,1057.56 r0 bottom
R51 "39 1%" N_0402 793.96,957.56 r0 bottom
R52 "39 1%" N_0402 493.92,910 r180 bottom
R53 "39 1%" N_0402 793.96,757.56 r0 bottom
R54 "39 1%" N_0402 794,2610 r0 bottom
R55 "39 1%" N_0402 792,2510 r0 bottom
R56 "39 1%" N_0402 792,2410 r0 bottom
R57 "39 1%" N_0402 794,2310 r0 bottom
R58 "39 1%" N_0402 794,2110 r0 bottom
R59 "39 1%" N_0402 493.96,1957.56 r180 bottom
R60 "39 1%" N_0402 794,1805.12 r0 bottom
R61 "39 1%" N_0402 794,1705.12 r0 bottom
R62 "39 1%" N_0402 794,1505.12 r0 bottom
R63 "39 1%" N_0402 493.36,1457 r180 bottom
R64 "39 1%" N_0402 493.96,1357.56 r180 bottom
R65 "39 1%" N_0402 493.96,1257.56 r180 bottom
R66 "39 1%" N_0402 493.96,1057.56 r180 bottom
R67 "39 1%" N_0402 493.96,957.56 r180 bottom
R68 "39 1%" N_0402 794,805.12 r0 bottom
R69 "39 1%" N_0402 493.96,757.56 r180 bottom
R70 "DNI" N_0402 547,2988 r270 bottom
R71 "2K" N_0603 2109,1088 r0 bottom
R72 "2K" N_0402 1211.82,572.4 r0 bottom
R73 "DNI" N_0603 2931,357 r90 bottom
R74 "DNI" N_0603 2967,454 r0 bottom
R75 "DNI" N_0603 219,166 r180 bottom
R76 "DNI" N_0603 252,259.9 r270 bottom
R77 "0" N_0402 2099,2816 r0 top
R78 "DNI" N_0603 2591,412 r180 top
R79 "DNI" N_0402 -52,1518 r270 bottom
R81 "DNI" N_0402 1005,685 r270 top
R82 "DNI" N_0402 1220,512 r180 top
R83 "DNI" N_0402 1732,1030 r180 top
R84 "DNI" N_0402 1910,738 r180 top
R85 "DNI" N_0402 2016,599 r90 top
R86 "15K" N_0402 1079,438 r0 top
R87 "15K" N_0402 1248,730 r90 top
R88 "0" N_0603 3044,117 r0 top
R89 "0" N_0603 138,612 r180 bottom
R90 "15K" N_0402 1795,539 r180 top
R91 "DNI" N_0402 2129,747 r90 top value=15K
R92 "15K" N_0402 1909,923 r0 top
R93 "15K" N_0402 1940,506 r270 top
U1 "142-BGA_MRAM" "BGA P1.0-142L" 1599.7,1841.45 r90 top locked
U2 "DNI" SOT223-PVR100AZ-B 2712.52,3120.71 r0 top
U3 "DNI" SOT223-PVR100AZ-B 1822.52,3142 r0 top
U4 "DNI" SOT223-PVR100AZ-B 868.52,3153 r0 top
U5 "BD2244G-M" SSOP6A 1747.13,921.6 r0 top
U6 "BD2244G-M" SSOP6A 2128.6,619.82 r90 top locked value=DNI
U7 "BD2244G-M" SSOP6A 1913,624 r0 top
U8 "DNI" TSSOP24 1328.78,2877.75 r0 bottom
U9 "DNI" ? 1730.18,2775.6 r180 bottom locked
U10 "BD2244G-M" SSOP6A 1243.27,611.2 r180 top
U11 "DNI" SOT223-PVR100AZ-B 3061,295.55 r270 top
U12 "DNI" SOT223-PVR100AZ-B 132,320.45 r90 top
U13 "DNI" PW16 2101,2745 r180 bottom locked
U14 "BD2244G-M" SSOP6A 1055.82,536.4 r0 top
U15 "DNI" TSOP_23 40,1394 r0 bottom
U16 "TLV757P-DBV" SOT23-5 1844,236 r0 top
U17 "BD2244G-M" SSOP6A 1844.6,427 r90 top
VCC "TP" "TEST POINT 40X20_010819" 2217,2941 r0 top value="COPPER FEATURE"
VCC1 "VCC" "TEST POINT" -24,2644 r180 top value="COPPER FEATURE"
VCC_M "TP" "TEST POINT 40X20_010819" 2032,739 r90 top value="COPPER FEATURE"
VCCE_REG "TP" "TEST POINT 40X20_010819" 2848,307 r180 top value="COPPER FEATURE"
VCCEXT "TP" "TEST POINT 40X20_010819" 2054.95,320 r90 top value="COPPER FEATURE"
VCCEXT1 "TP" "TEST POINT 40X20_010819" 1308,323 r270 top value="COPPER FEATURE"
VCCIO_REG "TP" "TEST POINT" 15,523 r90 top value="COPPER FEATURE"
VCCQ "" "TEST POINT" 3272,2831 r180 top value="COPPER FEATURE"
VCCQ1 "VCCQ" "TEST POINT 40X20_010819" 1116.82,691.4 r90 top value="COPPER FEATURE"
VDD "VDD" "TEST POINT" 1422,3266 r180 top value="COPPER FEATURE"
VPPW "" "TEST POINT" 3275,2531 r180 top value="COPPER FEATURE"
VWR "" "TEST POINT" 1222,3264 r90 top value="COPPER FEATURE"
W# "" "TEST POINT" 3280,1007 r90 top value="COPPER FEATURE"

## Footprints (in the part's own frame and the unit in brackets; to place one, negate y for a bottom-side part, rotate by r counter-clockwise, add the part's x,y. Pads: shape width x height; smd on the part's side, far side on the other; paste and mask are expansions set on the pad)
1X4_HDR [mil] "TH"
  rect 62x62 hole 25 mask+2: 1(-150,0)
  round 62 hole 25 mask+2: 2(-50,0) 3(50,0) 4(-150,100) 5(-50,100) 6(50,100)
  silkscreen extent -210,-55 110,150
1X5_HDR [mil] "TH"
  rect 62x62 hole 25 mask+2: 1(-150,0)
  round 62 hole 25 mask+2: 2(-50,0) 3(50,0) 4(150,0) 5(-150,-100) 6(-50,-100) 7(50,-100) 8(150,-100)
  silkscreen extent -200,-155 210,55
2X10-HEADER [mil] "TH"
  rect 55x55 hole 25 mask+2: 1(-950,-50)
  round 55 hole 25 mask+2: 2(-950,50) 3(-850,-50) 4(-850,50) 5(-750,-50) 6(-750,50) 7(-650,-50) 8(-650,50) 9(-550,-50) 10(-550,50) 11(-450,-50) 12(-450,50) 13(-350,-50) 14(-350,50) 15(-250,-50) 16(-250,50) 17(-150,-50) 18(-150,50) 19(-50,-50) 20(-50,50) 21(50,-50) 22(50,50) 23(150,-50) 24(150,50) 25(250,-50) 26(250,50) 27(350,-50) 28(350,50) 29(450,-50) 30(450,50) 31(550,-50) 32(550,50) 33(650,-50) 34(650,50) 35(750,-50) 36(750,50) 37(850,-50) 38(850,50) 39(950,-50) 40(950,50)
  silkscreen extent -1025,-100 1000,100
"BGA P1.0-142L" [mm]
  round 0.635 smd: A1(-6.5,7.5) A2(-5.5,7.5) A12(4.5,7.5) A13(5.5,7.5) A14(6.5,7.5) B1(-6.5,6.5) B14(6.5,6.5) C2(-5.5,5.5) C3(-4.5,5.5) C4(-3.5,5.5) C5(-2.5,5.5) C6(-1.5,5.5) C7(-0.5,5.5) C8(0.5,5.5) C9(1.5,5.5) C10(2.5,5.5) C11(3.5,5.5) C12(4.5,5.5) C13(5.5,5.5) C14(6.5,5.5) D2(-5.5,4.5) D3(-4.5,4.5) D4(-3.5,4.5) D5(-2.5,4.5) D6(-1.5,4.5) D7(-0.5,4.5) D8(0.5,4.5) D9(1.5,4.5) D10(2.5,4.5) D11(3.5,4.5) D12(4.5,4.5) D13(5.5,4.5) E2(-5.5,3.5) E3(-4.5,3.5) E4(-3.5,3.5) E5(-2.5,3.5) E6(-1.5,3.5) E7(-0.5,3.5) E8(0.5,3.5) E9(1.5,3.5) E10(2.5,3.5) E11(3.5,3.5) E12(4.5,3.5) E13(5.5,3.5) F2(-5.5,2.5) F3(-4.5,2.5) F4(-3.5,2.5) F5(-2.5,2.5) F6(-1.5,2.5) F7(-0.5,2.5) F8(0.5,2.5) F9(1.5,2.5) F10(2.5,2.5) F11(3.5,2.5) F12(4.5,2.5) F13(5.5,2.5) G2(-5.5,1.5) G3(-4.5,1.5) G4(-3.5,1.5) G5(-2.5,1.5) G10(2.5,1.5) G11(3.5,1.5) G12(4.5,1.5) G13(5.5,1.5) H2(-5.5,0.5) H3(-4.5,0.5) H4(-3.5,0.5) H5(-2.5,0.5) H10(2.5,0.5) H11(3.5,0.5) H12(4.5,0.5) H13(5.5,0.5) J2(-5.5,-0.5) J3(-4.5,-0.5) J4(-3.5,-0.5) J5(-2.5,-0.5) J10(2.5,-0.5) J11(3.5,-0.5) J12(4.5,-0.5) J13(5.5,-0.5) K2(-5.5,-1.5) K3(-4.5,-1.5) K4(-3.5,-1.5) K5(-2.5,-1.5) K10(2.5,-1.5) K11(3.5,-1.5) K12(4.5,-1.5) K13(5.5,-1.5) L2(-5.5,-2.5) L3(-4.5,-2.5) L4(-3.5,-2.5) L5(-2.5,-2.5) L6(-1.5,-2.5) L7(-0.5,-2.5) L8(0.5,-2.5) L9(1.5,-2.5) L10(2.5,-2.5) L11(3.5,-2.5) L12(4.5,-2.5) L13(5.5,-2.5) M2(-5.5,-3.5) M3(-4.5,-3.5) M4(-3.5,-3.5) M5(-2.5,-3.5) M6(-1.5,-3.5) M7(-0.5,-3.5) M8(0.5,-3.5) M9(1.5,-3.5) M10(2.5,-3.5) M11(3.5,-3.5) M12(4.5,-3.5) M13(5.5,-3.5) N2(-5.5,-4.5) N3(-4.5,-4.5) N4(-3.5,-4.5) N5(-2.5,-4.5) N6(-1.5,-4.5) N7(-0.5,-4.5) N8(0.5,-4.5) N9(1.5,-4.5) N10(2.5,-4.5) N11(3.5,-4.5) N12(4.5,-4.5) N13(5.5,-4.5) P2(-5.5,-5.5) P3(-4.5,-5.5) P4(-3.5,-5.5) P5(-2.5,-5.5) P6(-1.5,-5.5) P7(-0.5,-5.5) P8(0.5,-5.5) P9(1.5,-5.5) P10(2.5,-5.5) P11(3.5,-5.5) P12(4.5,-5.5) P13(5.5,-5.5) R1(-6.5,-6.5) R14(6.5,-6.5) T1(-6.5,-7.5) T2(-5.5,-7.5) T13(5.5,-7.5) T14(6.5,-7.5)
  round 0.762 hole 1.55 unplated mask+0.051: GUIDEPIN_1.55_NP(-12,-12)
  round 0.762 hole 2.05 unplated mask+0.051: GUIDEPIN_2.05_NP(12,12)
  round 4.572 hole 2.3 mask+0.051: HOLE2.3(-15,-10) HOLE2.3(-15,10) HOLE2.3(15,-10) HOLE2.3(15,10)
  round 0.762 on Mech2: ORIGIN(2.667,33.02)
  round 0.6 on Mech9: ""(0,0)
  Keep-Out Layer circle w0.127: c-12,-12 r1.016
  Keep-Out Layer circle w0.127: c12,12 r1.27
  silkscreen extent -20.45,-18 19,18
FB_2743019447 [mil]
  rect 71x118 smd mask+2: 1(-78.5,0) 2(78.5,0)
  round 50 on Mech2: ""(0,0)
  silkscreen extent -135,-75 135,75
FUDICIAL [mil]
  round 50 smd: FUDICIAL(0,0)
JUMPER_3PIN [mil]
  rect 62x62 hole 25 mask+2: 1(-100,0)
  round 62 hole 25 mask+2: 2(0,0) 3(100,0)
  silkscreen extent -150,-50 150,50
MUSB-05-S-B-SM-A [mm]
  rect 0.6x2.5 smd paste-0.127 mask+0.102: 1(1.6,0) 2(0.8,0) 3(0,0) 4(-0.8,0) 5(-1.6,0)
  rect 2x2.5 smd paste-0.127 mask+0.102: 6(4.45,0.3) 7(-4.45,0.3) 8(4.45,5.75) 9(-4.45,5.75)
  round 1 hole 1 unplated mask+0.051: ""(-2.2,2.88) ""(2.2,2.88)
  silkscreen extent -3.85,-0.47 3.85,8.73, body extent -5.35,-0.42 5.35,8.78, height 3.95
N_0402 [mil] "Chip Capacitor, Body 1.0x0.5mm, IPC High Density"
  rect 24x20 smd paste-5 mask+4: 1(-18,0)
  rect 24x20 smd paste-5 mask+2: 2(18,0)
  round 20 on Mech2: ""(0,0)
  silkscreen extent -36,-20 36,20, body extent -22,-12 22,12, height 51
N_0603 [mil]
  rect 38x40 smd paste-5 mask+4: 1(-30,0) 2(30,0)
  silkscreen extent -61,-33 62,32
N_0805 [mil]
  rect 35x55 smd paste-5 mask+4: 1(-37,0) 2(37,0)
  silkscreen extent -69,-40 69,40
N_1206 [mm]
  rect 1.6x1.8 smd paste-0.127 mask+0.102: 1(-1.425,0) 2(1.425,0)
  round 0.762 on Mech2: ORIGIN(0,0)
  silkscreen extent -2.51,-1.17 2.51,1.17, body extent -1.6,-0.8 1.6,0.8, height 1.5
POWER_JACK_PTH [mil] "POWER_JACK_PTH"
  round 170 hole 118 mask+2: GND(0,304) GNDBREAK(186,422) PWR(0,540)
  silkscreen extent -177,119 178,540
PW16 [mm] "TSOP, 16-Leads, Body 5.00x4.40mm, Pitch 0.65mm, IPC Medium Density"
  rect 1.5x0.45 smd paste-0.127 mask+0.051: 1(-2.9,2.275) 2(-2.9,1.625) 3(-2.9,0.975) 4(-2.9,0.325) 5(-2.9,-0.325) 6(-2.9,-0.975) 7(-2.9,-1.625) 8(-2.9,-2.275) 9(2.9,-2.275) 10(2.9,-1.625) 11(2.9,-0.975) 12(2.9,-0.325) 13(2.9,0.325) 14(2.9,0.975) 15(2.9,1.625) 16(2.9,2.275)
  silkscreen extent -1.85,-2.92 1.85,3.05, body extent -2.25,-2.55 2.25,2.55, height 1.2
SOT23-5 [mil] "SOT23-5"
  rect 28x39 smd paste-5 mask+4: 1(-37.4,-50.79) 2(0,-50.79) 3(38,-50.79) 4(38,52) 5(-37.4,52)
  silkscreen extent -50,-26 51,26
SOT223-PVR100AZ-B [mil]
  rect 50x60 smd paste-5 mask+1.97: 1(-90.55,-120) 2(0,-120) 3(90.55,-120)
  rect 141.73x60 smd paste-5 mask+1.97: 4(0,120)
  silkscreen extent -125,-75 125,75
SSOP6A [mm] "SOT23-5"
  rect 1.1x0.6 smd paste-0.127 mask+0.102: 1(-1.422,0.95) 2(-1.422,0) 3(-1.422,-0.95) 4(1.422,-0.95) 5(1.422,0) 6(1.422,0.95)
  silkscreen extent -0.81,-1.52 0.81,1.52
"TEST POINT" [mil] "TH"
  round 60 hole 25 mask+2: 1(0,0)
  silkscreen extent -40,-40 40,40
"TEST POINT 40X20_010819" [mil] "TH"
  round 40 hole 20 mask+2: 1(0,0)
  silkscreen extent -35,-35 35,35
TSOP_23 [mm]
  rect 1.22x0.62 smd paste-0.127 mask+0.102: 1(-1.31,0.95) 2(-1.31,0) 3(-1.31,-0.95) 4(1.31,-0.95) 5(1.31,0.95)
  silkscreen extent -2.33,-1.59 2.25,1.59
TSSOP24 [mm] "TSSOP, 24-Leads, Body 7.80x4.40mm, Pitch 0.65mm, IPC High Density"
  rect 1.25x0.4 smd paste-0.127 mask+0.102: 1(-2.825,3.575) 2(-2.825,2.925) 3(-2.825,2.275) 4(-2.825,1.625) 5(-2.825,0.975) 6(-2.825,0.325) 7(-2.825,-0.325) 8(-2.825,-0.975) 9(-2.825,-1.625) 10(-2.825,-2.275) 11(-2.825,-2.925) 12(-2.825,-3.575) 13(2.825,-3.575) 14(2.825,-2.925) 15(2.825,-2.275) 16(2.825,-1.625) 17(2.825,-0.975) 18(2.825,-0.325) 19(2.825,0.325) 20(2.825,0.975) 21(2.825,1.625) 22(2.825,2.275) 23(2.825,2.925) 24(2.825,3.575)
  silkscreen extent -1.8,-3.9 1.8,3.9
? [mm] "SOT23-5"
  rect 1.1x0.6 smd: 1(-1.3,0.95) 2(-1.3,0) 3(-1.3,-0.95) 4(1.3,-0.95) 5(1.3,0) 6(1.3,0.95)
  round 0.635 on Bottom Overlay: ""(-1.397,1.905)
  silkscreen extent -0.81,-1.52 0.81,1.52

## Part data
+5V_EXT/+3V +5V_USB/+3V A0 DQ0 E# G# GND1 GND2 GND3 GND4 GND5 GND6 GND7 GND8 GND9 GND10 GND11 GND12 GND13 GND14 VCC VCC1 VCC_M VCCE_REG VCCEXT VCCEXT1 VCCIO_REG VCCQ VCCQ1 VDD VPPW VWR W#: library part "TEST POINT 1"
C1 C2 C3 C4 C5 C6 C7 C8 C9 C10 C11 C12 C18 C19 C20 C21 C22 C51 C52 C53 C62 C63 C64 C67 C68 C70 C71 C72 C73 C74 C75 C76 C81 C82 C83 C84 C85: library part CAP
C13 C15 C65 C69: library part CAP, "CAP CER 10000PF 50V X7R 0603", Part Number=CC0603KPX7R9BB103
C14 C16 C66: library part CAP, "CAP CER 0.1UF 16V X7R 0603", Part Number=GCM188R71C104KA37D
C17: library part CAP, "CAP CER 4.7UF 6.3V X7R 0603", Part Number=CL10B475KQ8NQNC
C23 C24 C25 C26 C27 C28 C29 C30 C31 C32 C33 C34 C35 C36 C37 C38 C39 C40 C41 C42 C43 C44 C45 C46 C47 C48 C49 C50 C54 C55 C56 C57: library part CAP, "CAP CER 10000PF 50V X7R 0402", Part Number=GCM188R71C104KA37D
C58 C59 C60 C61 C77 C78 C79 C80: library part C-USC0603
C86 C87: library part CAP, "DNI", Part Number=CL10A105KB8NNNC
J1: library part 5PIN-JUMPER
J9: Part Number=5075BMR-05-SM-CR
L1 L4: library part FB, "FERRITE BEAD 120 OHM 0603 1LN"
L2 L3 L5 L6 L7: library part FB
L8: library part INDUCTOR
L9: library part INDUCTOR, "Ferrite Beads 43 SM BEAD Z=47 OHM @ 100MHz"
R1 R5 R6 R7 R8 R10 R11 R12 R13 R14 R15 R16 R17 R18 R19 R20 R21 R22 R23 R24 R25 R26 R27 R28 R29 R30 R31 R32 R33 R34 R35 R36 R37 R38 R39 R40 R41 R42 R43 R44 R45 R46 R47 R48 R49 R50 R51 R52 R53 R54 R55 R56 R57 R58 R59 R60 R61 R62 R63 R64 R65 R66 R67 R68 R69: library part R-US_R0603, "RES 39 OHM 1% 1/16W 0402", Part Number=RC0402FR-0739RL
R2 R3 R4 R70 R73 R74 R75 R76 R78 R79 R81 R82 R83 R84 R85 R88 R89: library part RES
R71: library part RES, "RES SMD 2K OHM 1% 1/10W 0603", Part Number=ERJ-U03F2001V
R72: library part RES, "RES 2K OHM 1% 1/10W 0603 SMD", Part Number=ERJ-U03F2001V
R77: library part RES, Part Number=RC0402JR-070RL
R86 R87 R90 R91 R92 R93: library part RES, "RES 2K OHM 1% 1/10W 0603 SMD", MANUFACTURER="Vishay Dale", Part Number=TNPW040215K0BEED
U2 U3 U4: library part PVR100AZ-B, "PVR100AZ-B3V3,115"
U5 U6 U7 U10 U14 U17: MANUFACTURER=ROHM
U8: library part AD7472, "IC ADC 12BIT SAR 24TSSOP", Part Number=AD7472BRUZ-REEL7
U9: library part LT6654AHS6-2.5, "IC VREF SERIES 0.05% TSOT23-6", Part Number=LT6654AHS6-2.5#TRPBF
U11 U12: library part LD1117STR, "\"Remove U11, U12, Short (connect) pins 1,2,3 for U11, and U12\""
U13: library part INA250A4_TSSOP16, "IC CURR SENSE 1 CIRCUIT 16TSSOP", Part Number=INA250A4PWR
U15: library part LTC6905, "IC OSC SILICON PROG TSOT23-5", Part Number=LTC6905IS5#TRMPBF

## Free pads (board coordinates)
  round 22 hole 8 mask+2: ""(129,2759) ""(131,2215) ""(131,2415) ""(131,2623) ""(138,1611) ""(187,2293) ""(370,2807) ""(523,2567) ""(833,1314) ""(888,760) ""(897,2350) ""(954,2291) ""(1255.3,1703.45) ""(1285.24,1624.91) ""(1285.24,2018.61) ""(1285.24,2057.98) ""(1290.86,1571.98) ""(1290.86,2110.92) ""(1299.19,1808.2) ""(1317,1546) ""(1343.79,1566.36) ""(1343.8,2116.54) ""(1363.98,1664.28) ""(1363.98,1703.65) ""(1363.98,1743.02) ""(1363.98,1939.87) ""(1363.98,1979.24) ""(1363.98,2057.98) ""(1369.6,1611.35) ""(1383.17,2116.54) ""(1408.97,1650.72) ""(1408.97,1808.2) ""(1408.97,1847.57) ""(1408.97,1886.94) ""(1408.97,2032.18) ""(1408.97,1729.46) ""(1448.34,1690.09) ""(1448.34,1914.07) ""(1448.34,1953.44) ""(1448.34,1992.81) ""(1448.34,2032.18) ""(1448.34,1729.46) ""(1448.34,1768.83) ""(1448.34,1808.2) ""(1448.34,1847.57) ""(1461.91,2077.17) ""(1487.71,1540.94) ""(1487.71,1650.72) ""(1487.71,1690.09) ""(1487.71,1729.46) ""(1487.71,1953.44) ""(1487.71,1992.81) ""(1487.71,2032.18) ""(1487.71,1768.83) ""(1487.71,1914.07) ""(1492.98,2133.05) ""(1511,1559) ""(1527.08,1690.09) ""(1527.08,1992.81) ""(1527.08,1650.72) ""(1536.7,1821.76) ""(1536.7,1861.13) ""(1540.65,1605.73) ""(1540.65,1778.45) ""(1540.65,1904.45) ""(1566.45,1690.09) ""(1566.45,1992.81) ""(1566.45,2032.18) ""(1566.45,1650.72) ""(1580.02,1605.73) ""(1580.02,1904.45) ""(1619.39,1605.73) ""(1619.39,2077.17) ""(1619.39,2190.09) ""(1629,1475) ""(1632.95,1650.72) ""(1632.95,1690.09) ""(1632.95,1992.81) ""(1632.95,2032.18) ""(1658.76,1554.51) ""(1658.76,1904.45) ""(1672.32,1690.09) ""(1672.32,2032.18) ""(1672.32,1992.81) ""(1684.56,1847.57) ""(1684.56,1886.94) ""(1698.13,2077.17) ""(1711.69,1690.09) ""(1711.69,1729.46) ""(1711.69,1768.83) ""(1711.69,1808.2) ""(1711.69,1992.81) ""(1711.69,1650.72) ""(1737.5,2077.17) ""(1751.06,1650.72) ""(1751.06,1690.09) ""(1751.06,1729.46) ""(1751.06,1768.83) ""(1751.06,1808.2) ""(1751.06,1874.7) ""(1751.06,1914.07) ""(1751.06,1953.44) ""(1751.06,1992.81) ""(1751.06,2032.18) ""(1756,1002) ""(1757,960) ""(1769,983) ""(1776.87,2077.17) ""(1782,1002) ""(1783,1026) ""(1790.43,1611.35) ""(1790.43,1650.72) ""(1790.43,1690.09) ""(1790.43,1729.46) ""(1790.43,1768.83) ""(1790.43,1808.2) ""(1790.43,1874.7) ""(1790.43,1914.07) ""(1790.43,1953.44) ""(1790.43,1992.81) ""(1790.43,2032.18) ""(1795,983) ""(1807,1002) ""(1807,1026) ""(1816.24,1504.36) ""(1816.24,2077.17) ""(1820,983) ""(1829.8,1611.35) ""(1829.8,1992.81) ""(1832,1002) ""(1832,1026) ""(1834,961) ""(1835.42,1664.28) ""(1835.42,1703.65) ""(1835.42,1743.02) ""(1835.42,1782.39) ""(1835.42,1900.5) ""(1869.17,1571.98) ""(1869.17,2110.92) ""(1897,1801) ""(1908.54,1571.98) ""(1908.54,1611.35) ""(1908.54,2110.92) ""(1914.16,2057.98) ""(1942.73,1992.81) ""(1945.2,1703.65) ""(1945.2,1900.5) ""(2049,2817) ""(2080,2775) ""(2092,1635) ""(2119,2776) ""(2150,2816)
  round 60 on Mech9: ""(479,1807.56) ""(479,2707.56)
